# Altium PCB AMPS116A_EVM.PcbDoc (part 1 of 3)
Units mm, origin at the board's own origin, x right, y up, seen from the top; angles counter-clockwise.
Board outline 95 x 85 mm, 4 copper layers (Top Layer, Mid-Layer 1, Mid-Layer 2, Bottom Layer), stack 1.554 mm thick; 252 components, 134 nets, 806 pads, 625 vias.
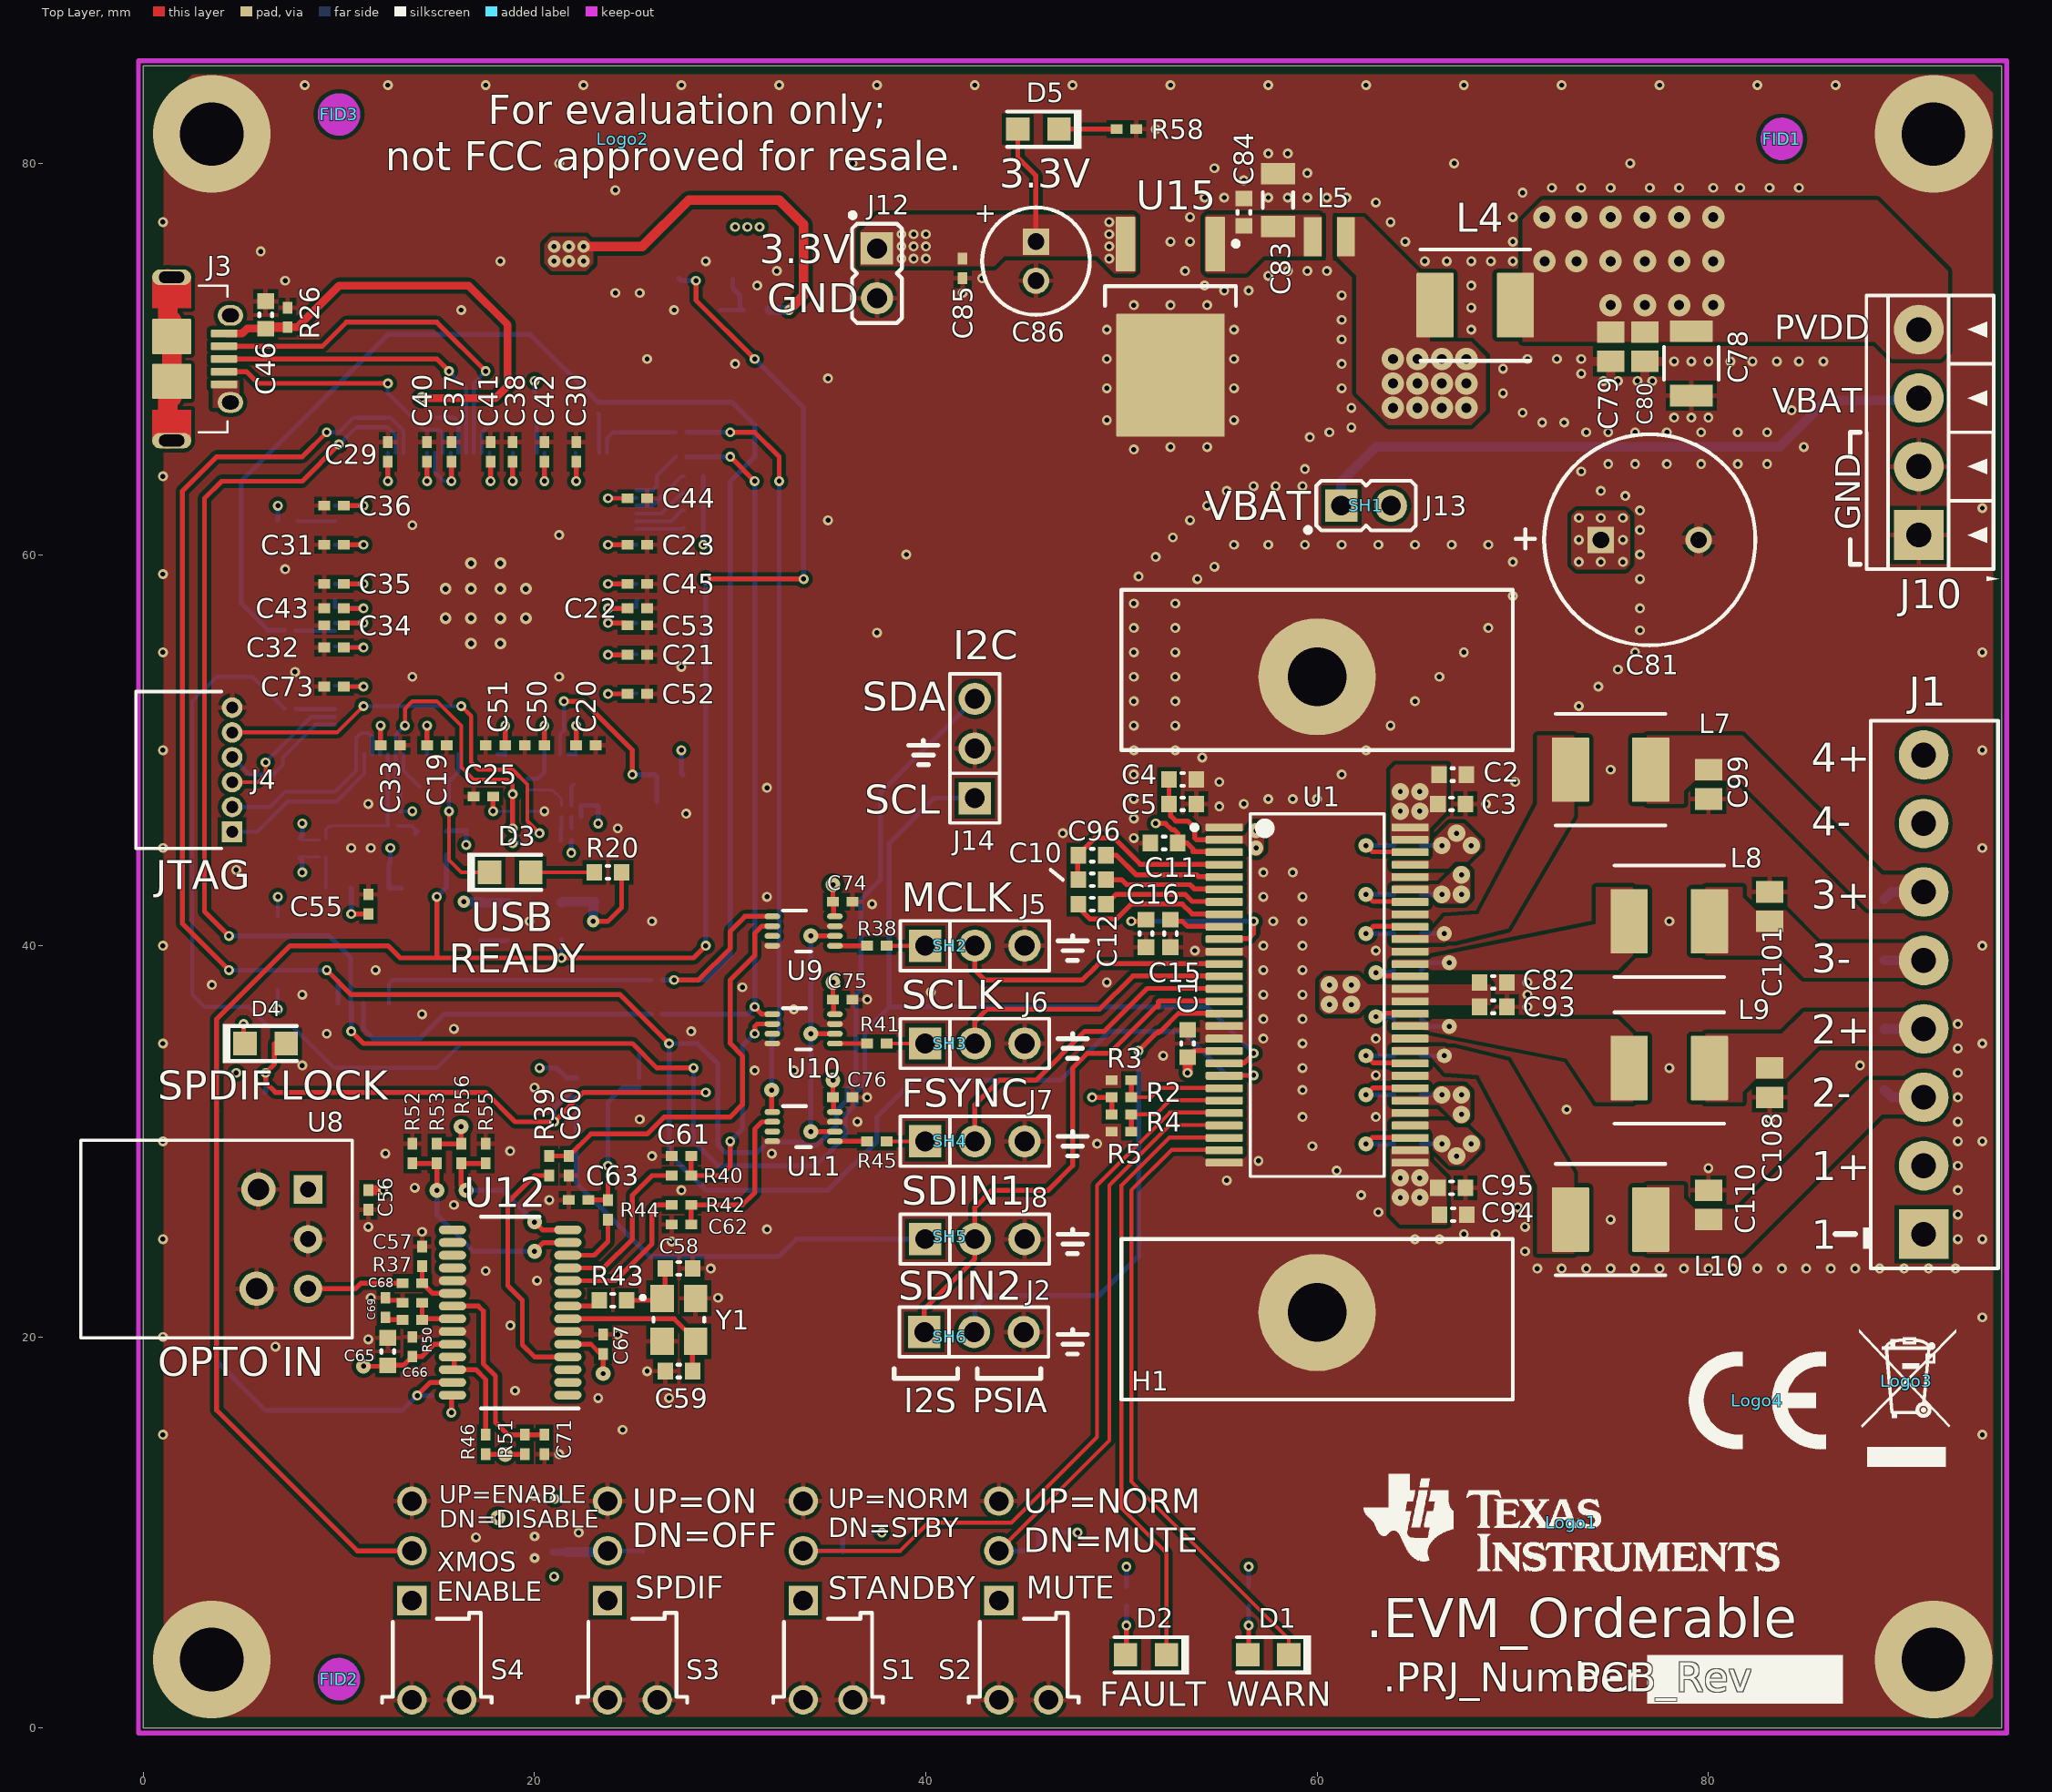
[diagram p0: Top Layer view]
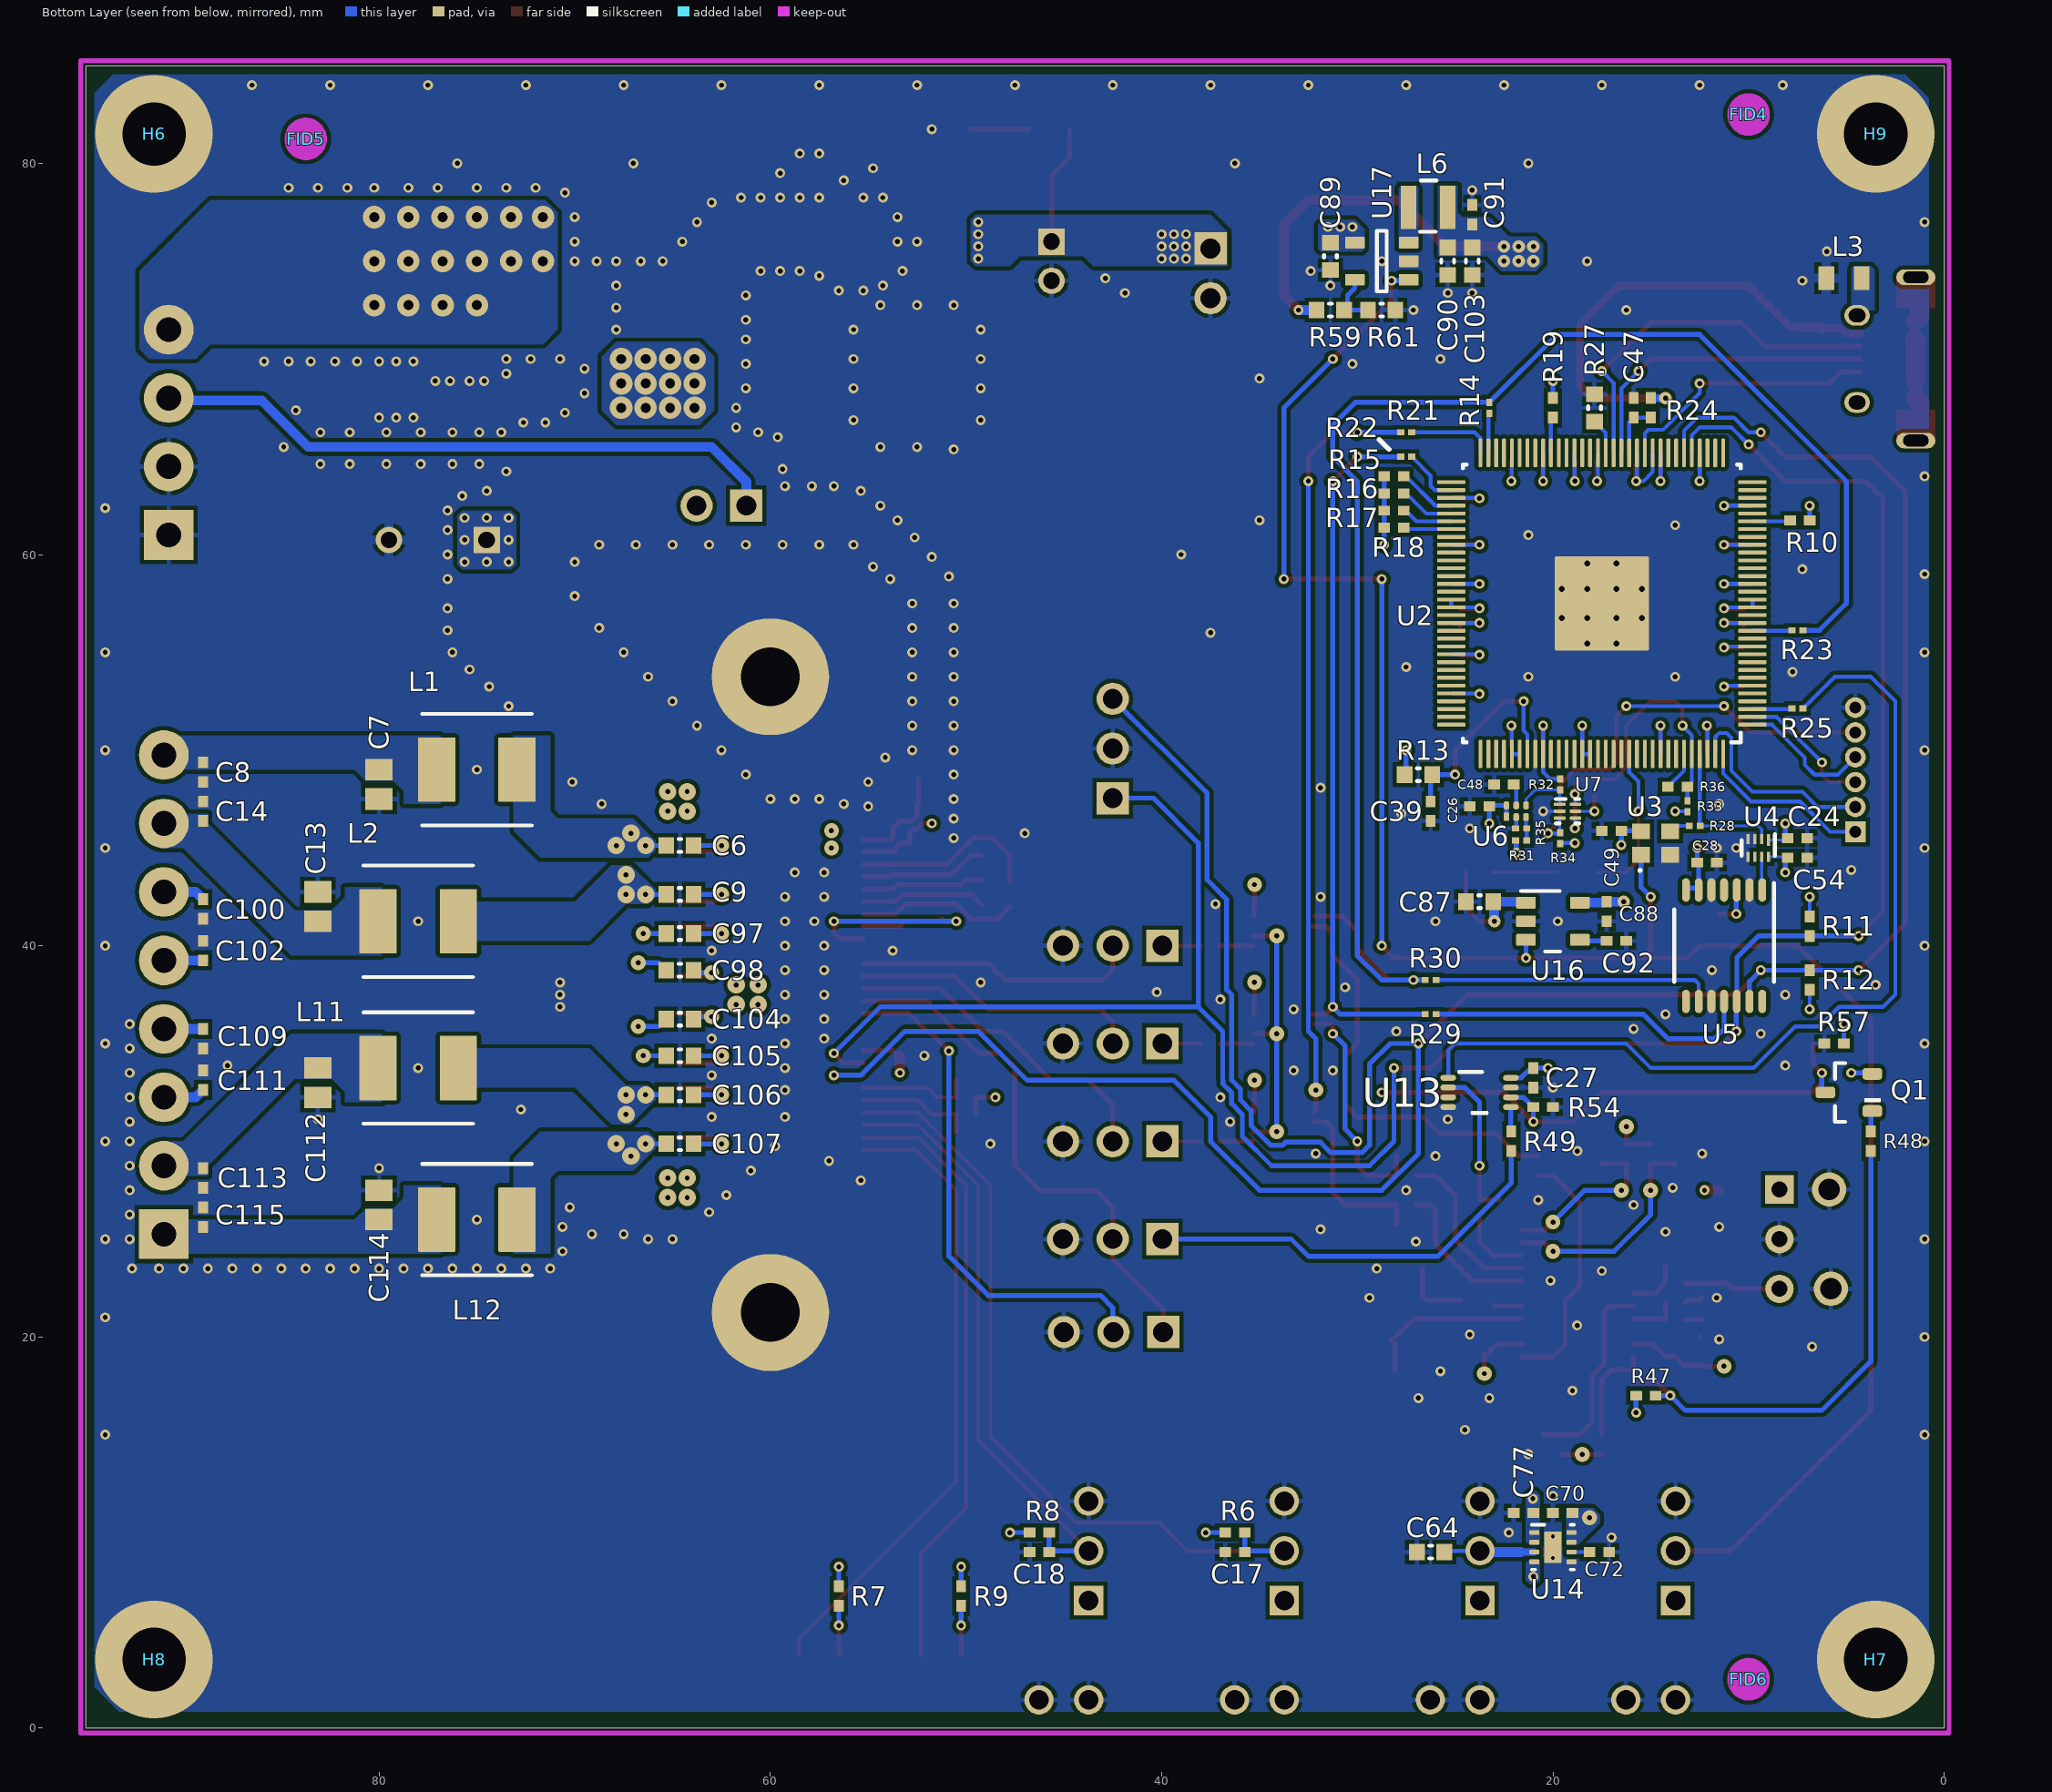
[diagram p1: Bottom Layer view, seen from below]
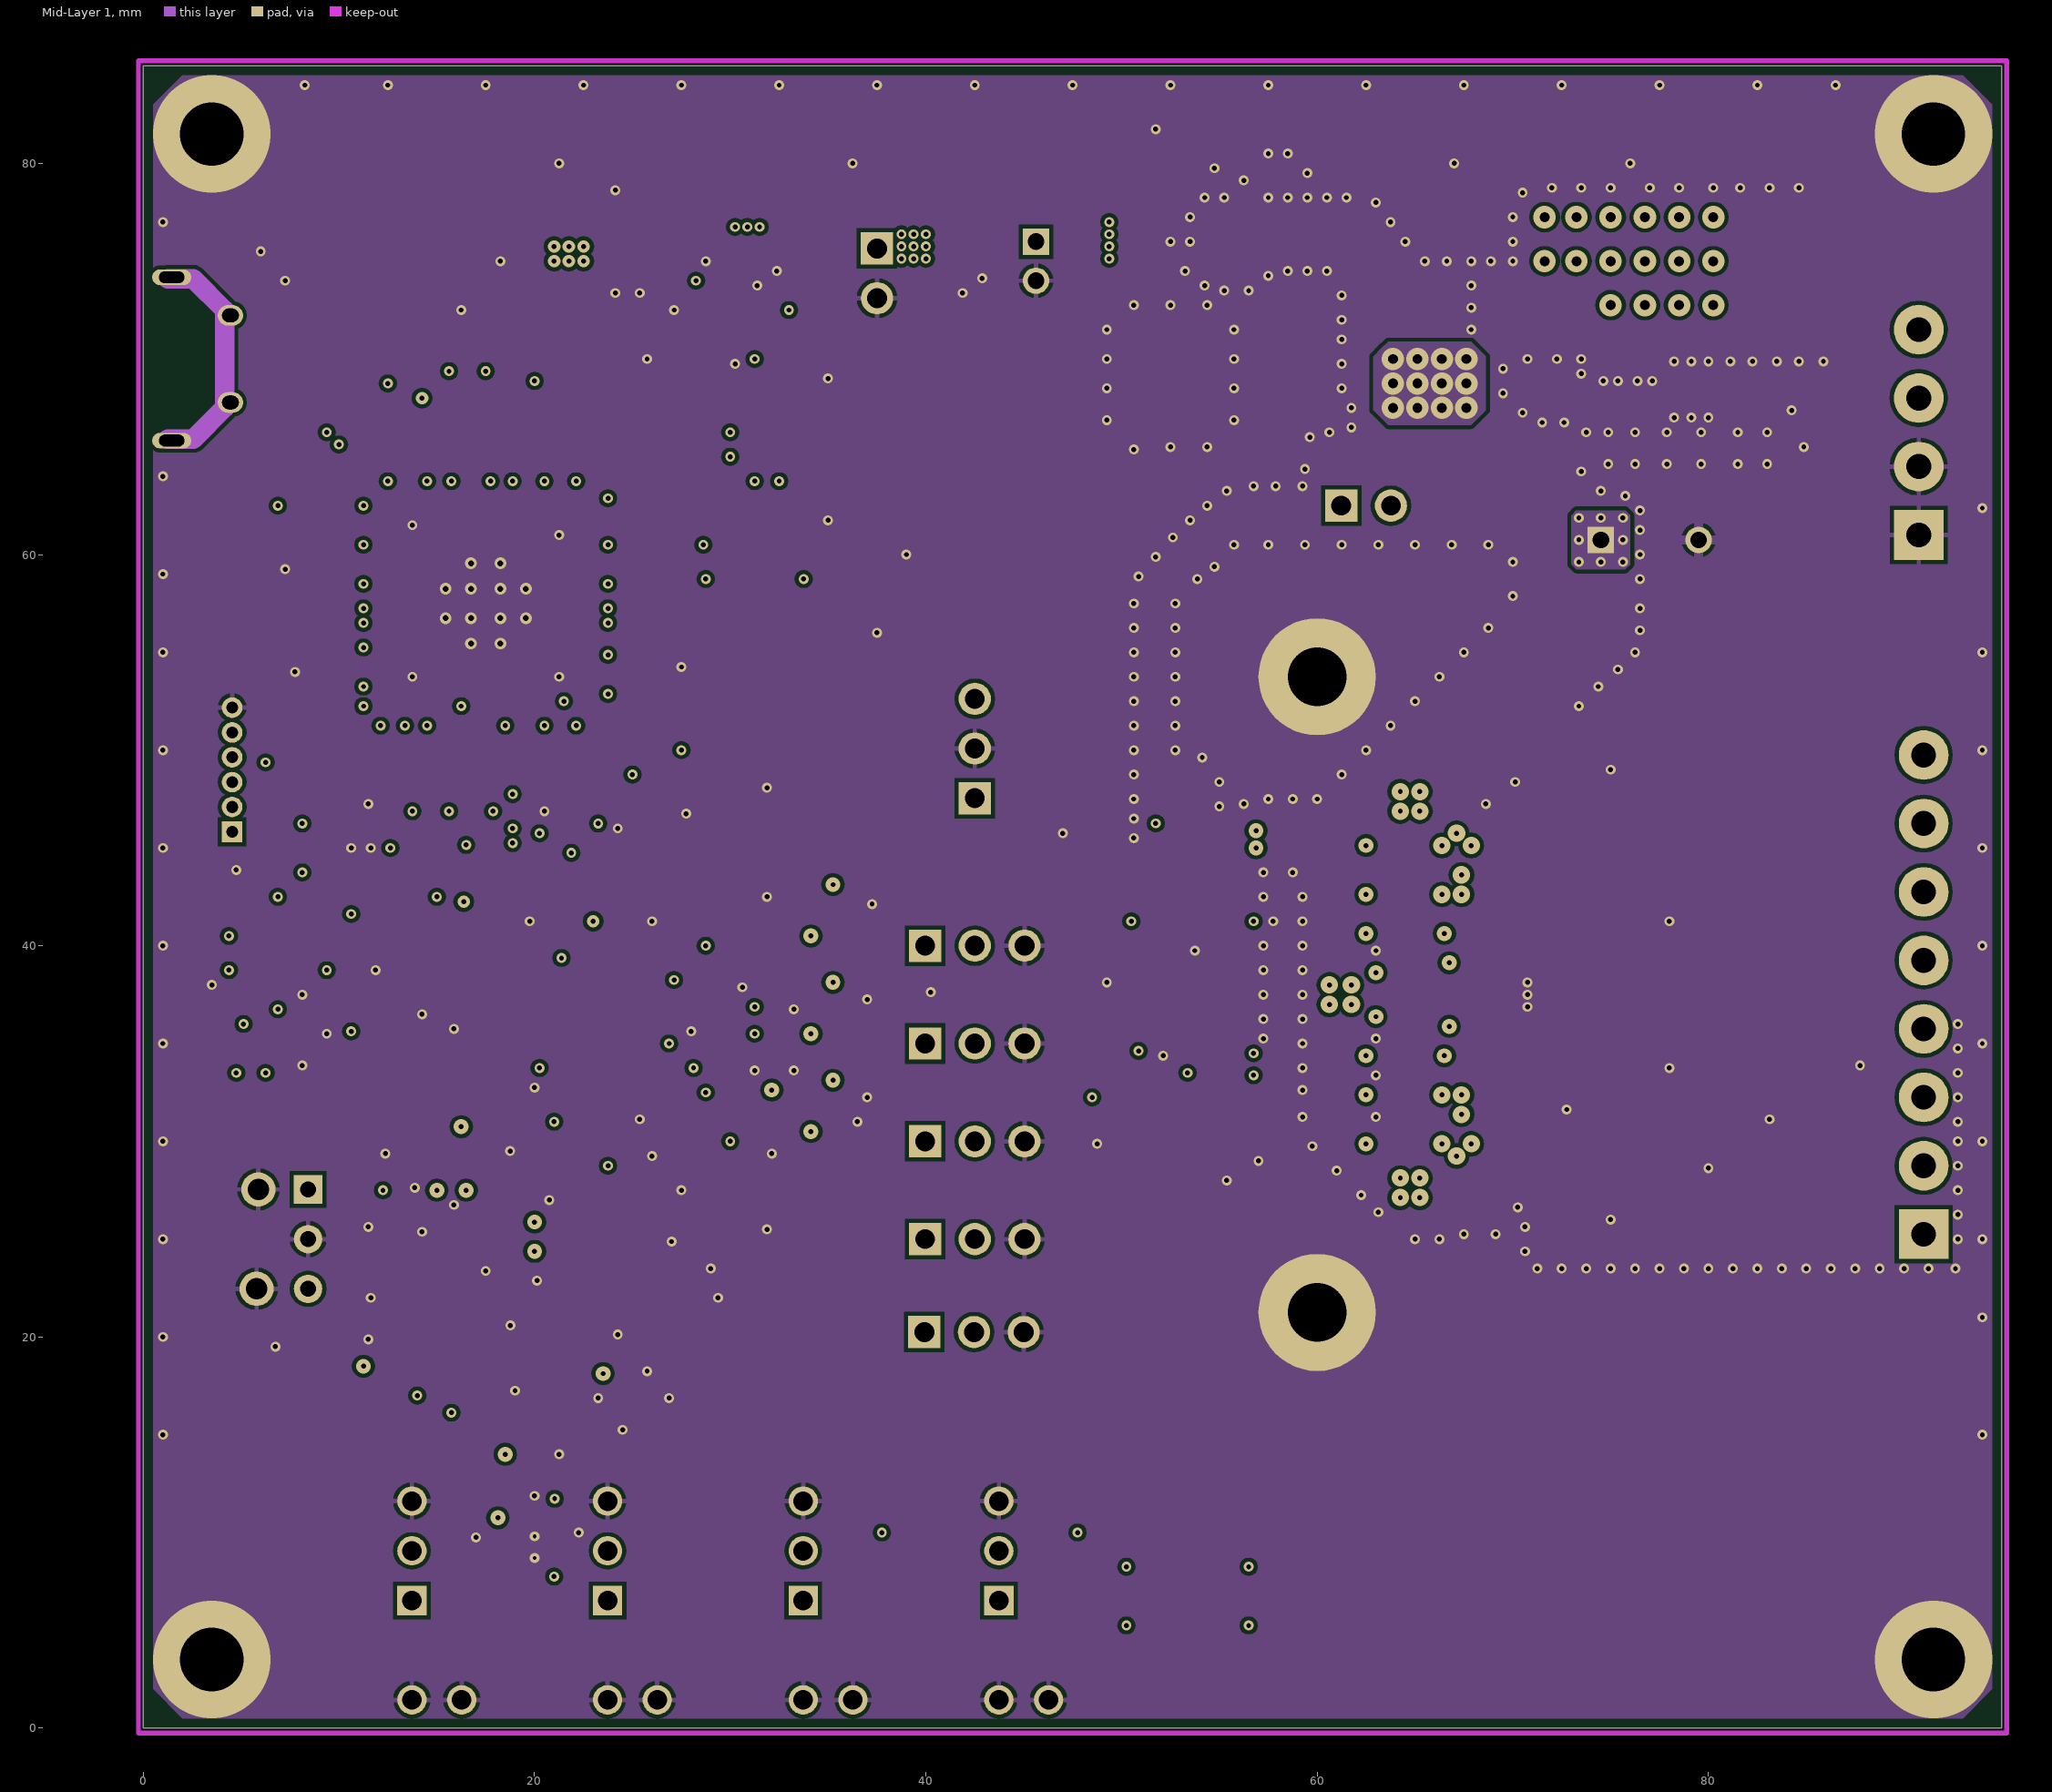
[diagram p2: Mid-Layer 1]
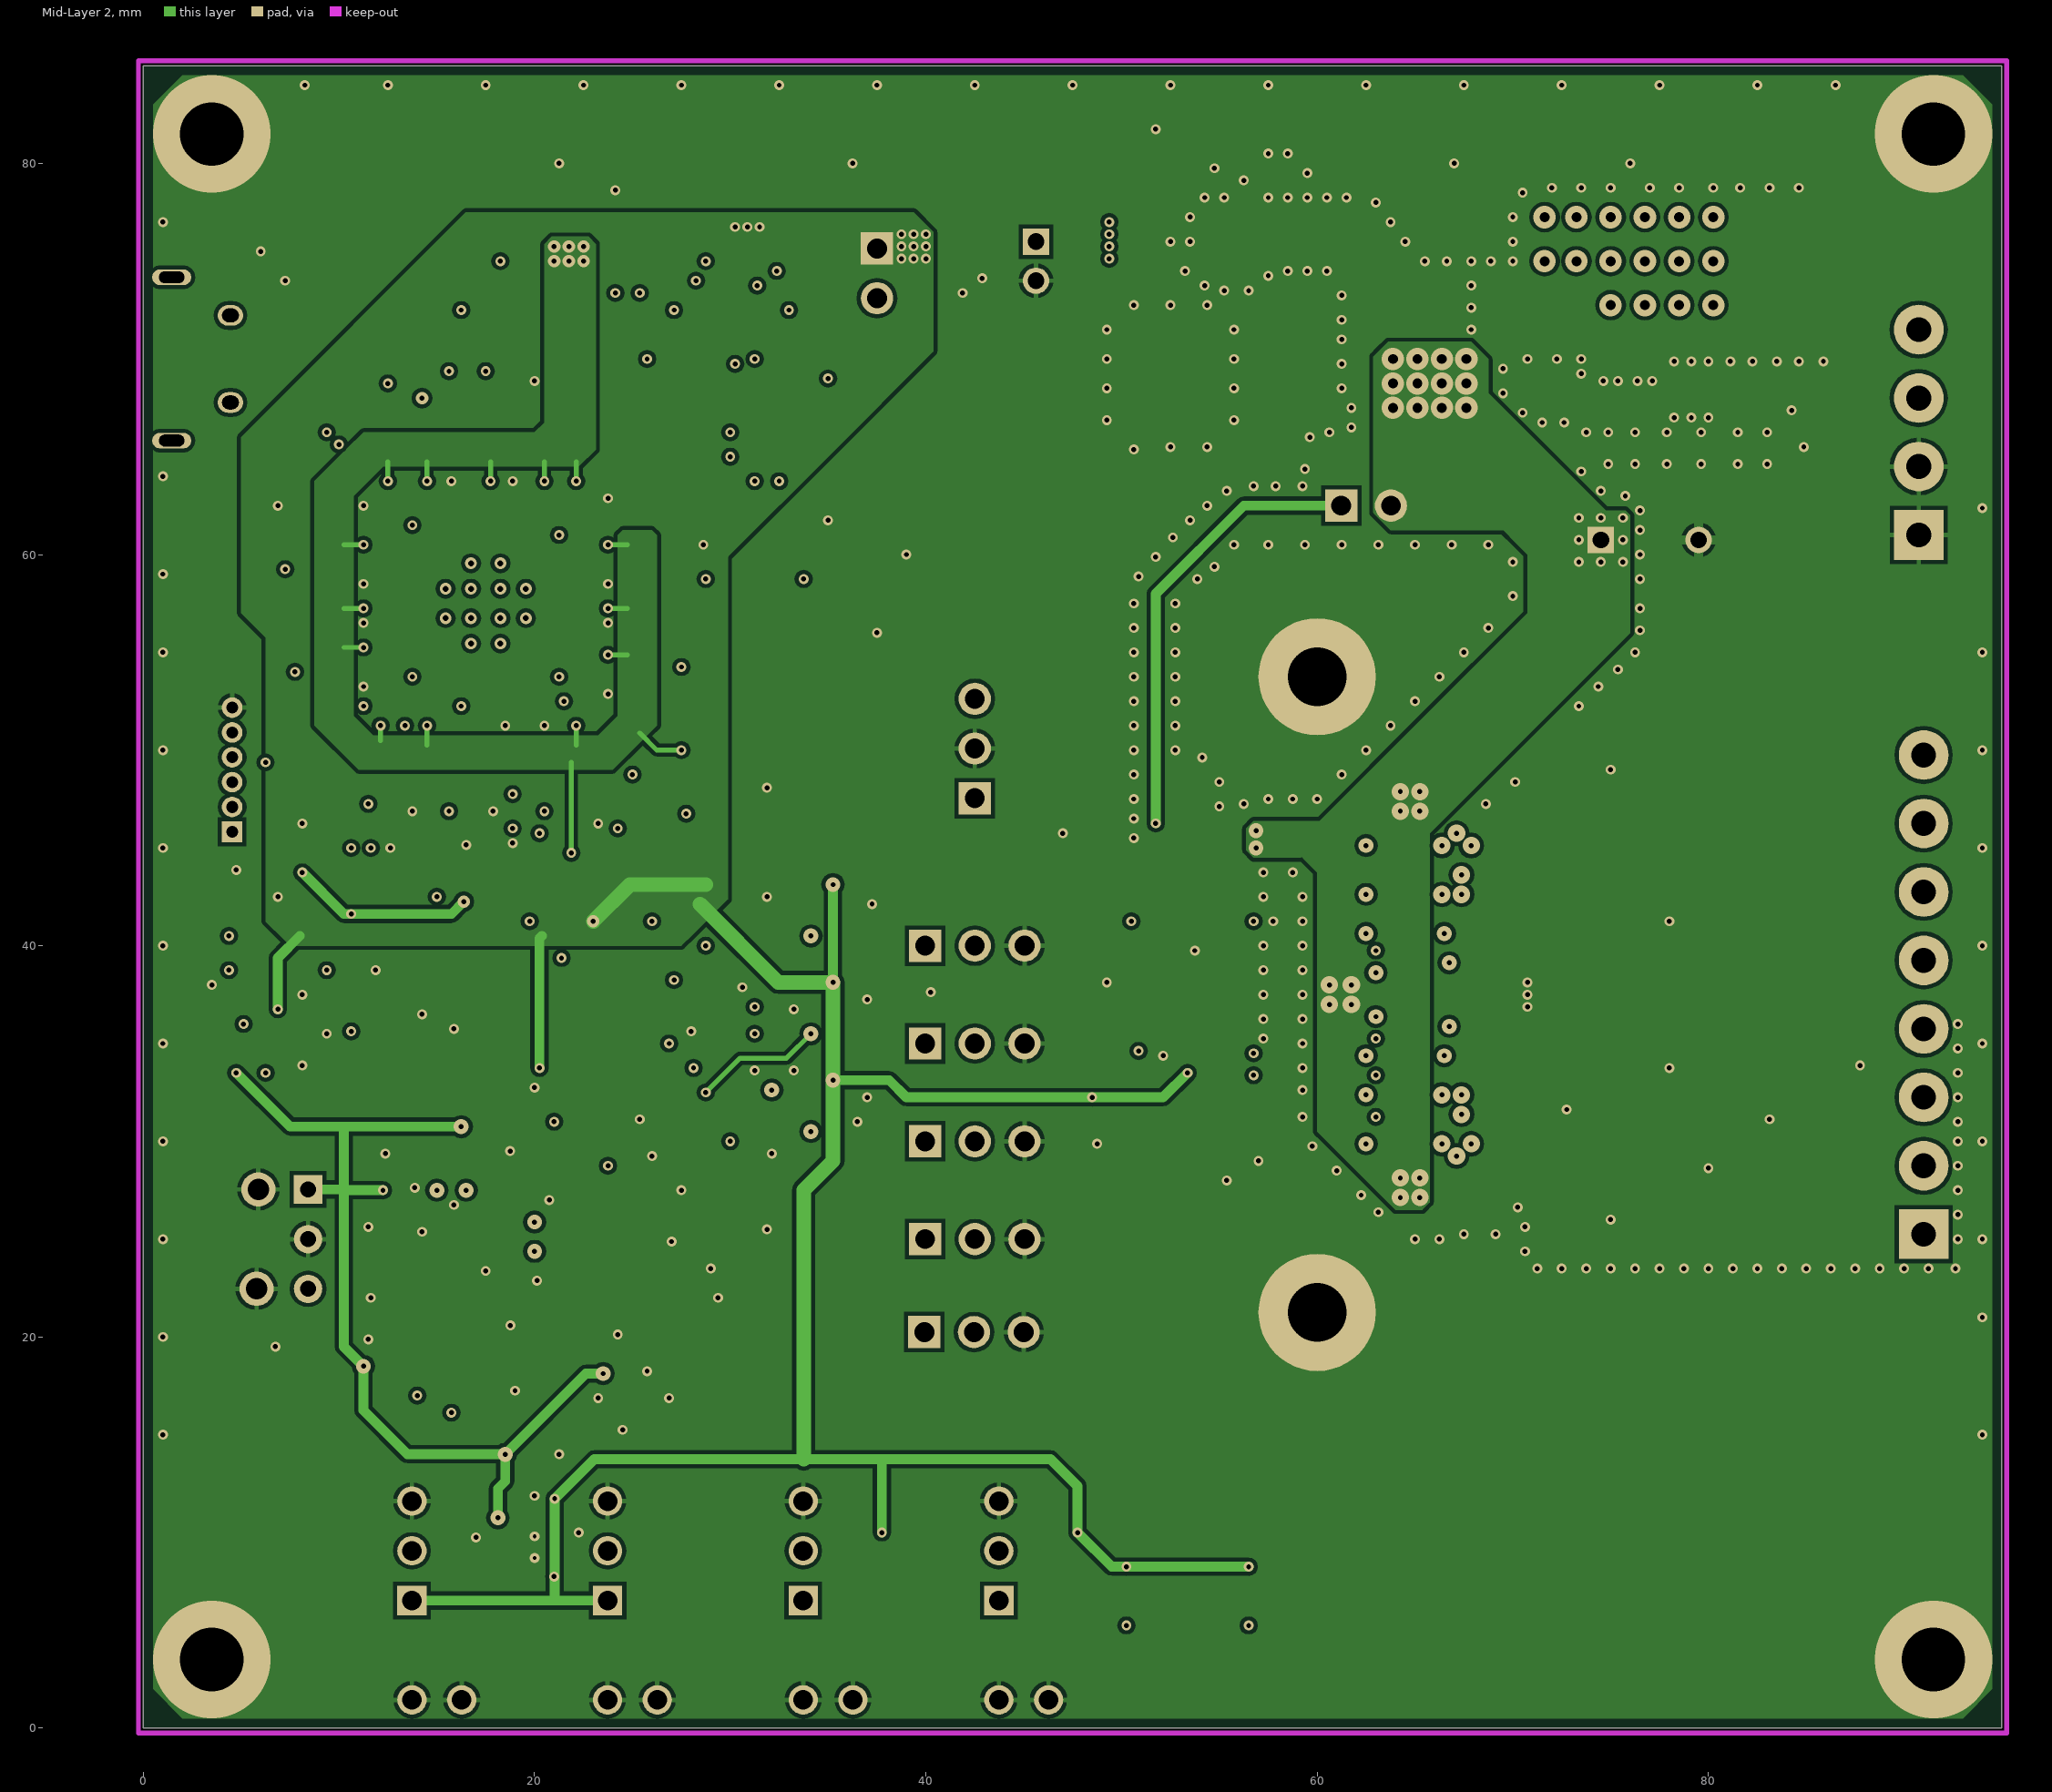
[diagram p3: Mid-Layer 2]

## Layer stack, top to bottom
Top Solder: solder mask 0.0102, Solder Resist, Dk 3.5
Top Layer: signal copper 0.0356
Dielectric1: core 0.2032, FR-4, Dk 4.2
Mid-Layer 1: signal copper 0.0356
Dielectric3: dielectric 1.0058, FR-4, Dk 4.2
Mid-Layer 2: signal copper 0.0356
Dielectric2: dielectric 0.2032, FR-4, Dk 4.2
Bottom Layer: signal copper 0.0356
Bottom Solder: solder mask 0.0102, Solder Resist, Dk 3.5

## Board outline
0,0 95,0 95,85 0,85

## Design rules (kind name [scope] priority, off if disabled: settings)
AcuteAngle [All] p1: minimum=4.50000000000000E+0001 checktracksonly=FALSE
AssemblyTestPointUsage [All] p1: valid=2
BoardOutlineClearance "Parts At Edge" [(InComponentClass('Edge Parts'))] p1: gap=0 ignorepadtopadclearanceinfootprint=FALSE
BoardOutlineClearance BoardOutlineClearance_MountingHoles [OnCopper and InComponentClass('Mounting Holes')] p2: gap=0.25 ignorepadtopadclearanceinfootprint=FALSE
BoardOutlineClearance BoardOutlineClearance_Poly [OnCopper and IsPoly] p3: gap=0.45 ignorepadtopadclearanceinfootprint=FALSE
BoardOutlineClearance [OnCopper and Not InComponentClass('Logo') and not InComponentClass('FiducialMark') and not InRegion(1000,500,4000,800) and not InPoly] p4: gap=0.25 ignorepadtopadclearanceinfootprint=FALSE
Clearance "Clearance LibErrors" [HasFootprint('DSF*') or HasFootprint('DQE*') or HasFootprint('RLT*')] p1: gap=0.2 ignorepadtopadclearanceinfootprint=TRUE except(0: Arc-Hole Track-Hole SMDPad-Hole THPad-Hole Via-Hole Fill-Hole Poly-Hole Region-Hole Text-Hole; 0.15: Arc-Arc Arc-Track Arc-SMDPad Track-Track Track-SMDPad)
Clearance Clearance_Keepouts [((IsTrack Or IsArc) And Not InPoly) And IsFree and IsKeepOut vs ((IsTrack Or IsArc) And Not InPoly) And IsFree and IsKeepOut] p2: gap=0 ignorepadtopadclearanceinfootprint=FALSE
Clearance Clearance_Poly [InPolygon] p3: gap=0.2 ignorepadtopadclearanceinfootprint=FALSE except(0: Arc-Hole Track-Hole SMDPad-Hole THPad-Hole Via-Hole Fill-Hole Poly-Hole Region-Hole Text-Hole)
Clearance Clearance_FiducialMark [IsKeepOut and InComponentClass('FiducialMark') vs IsPad and InComponentClass('FiducialMark')] p4: gap=0 ignorepadtopadclearanceinfootprint=FALSE
Clearance [All] p5: gap=0.2 ignorepadtopadclearanceinfootprint=FALSE except(0: Arc-Hole Track-Hole SMDPad-Hole THPad-Hole Via-Hole Fill-Hole Poly-Hole Region-Hole Text-Hole)
ComponentClearance "HeatSink Clearance" [InComponentClass('HeatSink')] p1: gap=0 collisioncheckmode=3 verticalgap=0 showdistances=FALSE
ComponentClearance ComponentClearance_MountingHoles_FiducialMarks [InComponentClass('Mounting Holes') vs InComponentClass('FiducialMark')] p2: gap=0.25 collisioncheckmode=3 verticalgap=0 showdistances=FALSE
ComponentClearance ComponentClearance_Shunt [InComponentClass('Header') vs InComponentClass('Shunt')] p3: gap=0 collisioncheckmode=3 verticalgap=0 showdistances=FALSE
ComponentClearance ComponentClearance_Logo [InComponentClass('Logo')] p4: gap=0.25 collisioncheckmode=3 verticalgap=0 showdistances=FALSE
ComponentClearance ComponentClearance_MountingHoles [InComponentClass('Mounting Holes') vs InComponentClass('Mounting Holes')] p5: gap=0 collisioncheckmode=3 verticalgap=0 showdistances=FALSE
ComponentClearance ComponentClearance_SmallPassives [HasFootprint('0201*') or HasFootprint('0402*') or HasFootprint('0603*') or HasFootprint('0805*') or HasFootprint('1008*') or HasFootprint('12*') or HasFootprint('Abracon*') or HasFootprint('DBV*') or HasFootprint('DCU*') or HasFootprint('DFE*') or HasFootprint('DS*') or HasFootprint('DQE*') or HasFootprint('DRY*') or HasFootprint('FDSD*') or HasFootprint('KVU*') or HasFootprint('NFZ*') or HasFootprint('PW*') or HasFootprint('RLT*') or HasFootprint('SOT*') or HasFootprint('SW*') or HasFootprint('VLS*') vs HasFootprint('0201*') or HasFootprint('0402*') or HasFootprint('0603*') or HasFootprint('0805*') or HasFootprint('1008*') or HasFootprint('12*') or HasFootprint('Abracon*') or HasFootprint('DBV*') or HasFootprint('DCU*') or HasFootprint('DFE*') or HasFootprint('DS*') or HasFootprint('DQE*') or HasFootprint('DRY*') or HasFootprint('FDSD*') or HasFootprint('KVU*') or HasFootprint('NFZ*') or HasFootprint('PW*') or HasFootprint('RLT*') or HasFootprint('SOT*') or HasFootprint('SW*') or HasFootprint('VLS*')] p6: gap=0.2 collisioncheckmode=3 verticalgap=0 showdistances=FALSE
ComponentClearance ComponentClearance_THtoSMT [IsThruComponent vs IsSMTComponent] p7: gap=0.25 collisioncheckmode=3 verticalgap=0 showdistances=FALSE
ComponentClearance ComponentClearance_THtoTH [IsThruComponent vs IsThruComponent] p8: gap=0.25 collisioncheckmode=3 verticalgap=0 showdistances=FALSE
ComponentClearance [All] p9: gap=0.762 collisioncheckmode=3 verticalgap=0.254 showdistances=FALSE
DiffPairsRouting [All] p1: maxlimit=2.54 minlimit=0.254 mostfreqgap=0.254 toplayer_minwidth=0.381 toplayer_maxwidth=0.381 toplayer_prefwidth=0.381 midlayer1_minwidth=0.381 midlayer1_maxwidth=0.381 midlayer1_prefwidth=0.381 midlayer2_minwidth=0.381 midlayer2_maxwidth=0.381 midlayer2_prefwidth=0.381 bottomlayer_minwidth=0.381 bottomlayer_maxwidth=0.381 bottomlayer_prefwidth=0.381 maxuncoupledlength=25.4
FabricationTestPointUsage TestPointUsage [All] p1: valid=2 allowmultiple=FALSE
FabricationTestpoint Testpoint [All] p1: side=3 testpointundercomponent=TRUE minsize=1.016 maxsize=2.54 preferedsize=1.524 minholesize=0 maxholesize=1.016 preferedholesize=0.813 testpointgrid=0.025 allowsidetop=TRUE allowsidebottom=TRUE usegrid=TRUE gridtolerance=0
FanoutControl Fanout_LCC [IsLCC] p1: bgadir=Out bgaviamode=Centered fanoutstyle=Auto fanoutdirection=Alternating viagrid=0.025 // Fanout_LCC (Default Rule)
FanoutControl Fanout_BGA [IsBGA] p2: bgadir=Out bgaviamode=Centered fanoutstyle=Auto fanoutdirection=Alternating viagrid=0.025 // Fanout_BGA (Default Rule)
FanoutControl Fanout_Default [All] p4: bgadir=Out bgaviamode=Centered fanoutstyle=Auto fanoutdirection=Alternating viagrid=0.025 // Fanout_Default (Default Rule)
FanoutControl Fanout_Small [(CompPinCount < 5)] p5: bgadir=Out bgaviamode=Centered fanoutstyle=Auto fanoutdirection=OutThenIn viagrid=0.025 // Fanout_Small (Default Rule)
Height [All] p1: minheight=0 maxheight=35 prefheight=12.7
HoleSize [All] p1: absolutevalues=TRUE maxlimit=6.375 minlimit=0.2 maxpercent=80.000 minpercent=20.000
MinimumAnnularRing MinimumAnnularRing_ThermalPadVias [IsVia and InAnyComponent] p1: minimumring=0.15
MinimumAnnularRing [All] p2: minimumring=0.127
MinimumSolderMaskSliver "MinSolderMaskSliver LibErrors" [HasFootprint('DSF*') or HasFootprint('DQE*')] p1: minsoldermaskwidth=0.064
MinimumSolderMaskSliver MinimumSolderMaskSliver_Logo [InComponentClass('Logo') vs InComponentClass('Logo')] p2: minsoldermaskwidth=0.018
MinimumSolderMaskSliver [All] p3: minsoldermaskwidth=0.1
PlaneConnect [All] p1: planeconnectstyle=Relief reliefexpansion=0.254 reliefentries=4 reliefconductorwidth=0.254 reliefairgap=0.254
PolygonConnect "Post GND Full Flood" [InComponentClass('GND Full Flood') vs InNet('GND')] p1: connectstyle=Direct reliefconductorwidth=0.254 reliefentries=4 polygonreliefangle="90 Angle" airgapwidth=0.254
PolygonConnect "GND Thermals 0.5mm" [InComponentClass('GND Thermals 0.5mm') vs InNet('GND')] p2: connectstyle=Relief reliefconductorwidth=0.5 reliefentries=4 polygonreliefangle="90 Angle" airgapwidth=0.2
PolygonConnect "GND Thermals 0.25mm" [InComponent('C*') or InComponent('D*') or InComponent('J*') or  InComponent('R*') or InComponent('S*') or InComponent('TP*') or  InComponent('Y*') or InComponent('U8') or InComponent('U16') vs InNet('GND')] p3: connectstyle=Relief reliefconductorwidth=0.25 reliefentries=4 polygonreliefangle="90 Angle" airgapwidth=0.2
PolygonConnect "Pre Flood" [All] p4: connectstyle=Direct reliefconductorwidth=0.254 reliefentries=4 polygonreliefangle="90 Angle" airgapwidth=0.254
RoutingVias ThermalPadVias [IsVia and InAnyComponent] p1: holewidth=0.2 width=0.5 viastyle="Through Hole" minholewidth=0.2 minwidth=0.5 maxholewidth=0.33 maxwidth=0.6
RoutingVias [All] p2: holewidth=0.254 width=0.508 viastyle="Through Hole" minholewidth=0.2 minwidth=0.508 maxholewidth=3.25 maxwidth=6.5
SilkToBoardRegionClearance [Not ((IsComment or IsDesignator) And (Hide <> 'False')) and not InRegion(1000,500,4000,800)] p1:
SilkToSilkClearance SilkToSilkClearance_Pb-FreeLogo [(HasFootprint('Pb-Free_Overlay_Medium') OR HasFootprint('Pb-Free_Overlay_Small')) vs (HasFootprint('Pb-Free_Overlay_Medium') OR HasFootprint('Pb-Free_Overlay_Small'))] p1: silktosilkclearance=0
SilkToSilkClearance [All] p2: silktosilkclearance=0.102
SilkToSolderMaskClearance "SilkToSolderMask LibErrors" [All vs HasFootprint('DSF*') or HasFootprint('LED*') or HasFootprint('LTST*')] p1: minsilkscreentomaskgap=0.038 clearancetoexposedcopper=FALSE
SilkToSolderMaskClearance SilkToComponentPadClearance [(IsPad or IsFill or IsRegion) and InAnycomponent] p2: minsilkscreentomaskgap=0.127 clearancetoexposedcopper=TRUE
SilkToSolderMaskClearance "Silk to Solder Mask Opening" [All] p3: minsilkscreentomaskgap=0.102 clearancetoexposedcopper=FALSE
SolderMaskExpansion [All] p1: expansion=0.05
Width [All] p1: maxlimit=2 minlimit=0.15 preferedwidth=0.25 toplayer_prefwidth=0.2 midlayer1_minwidth=0.2 midlayer1_maxwidth=1 midlayer2_minwidth=0.2 midlayer2_maxwidth=1 bottomlayer_prefwidth=0.2 minimp=50.000000 maximp=50.000000 favimp=50.000000 checkconnectedcopper=TRUE
14 further rules are at their usual default settings.

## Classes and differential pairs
component class "GND Thermals Full Flood": C89 C90 C91 C103
component class "GND Thermals 0.5mm": C79 C80 C81 L3
component class "GND Full Flood": C2 C4 C8 C14 C82 C83 C84 C94 C100 C102 C109 C111 C113 C115 R3 R5
component class Shunt: SH1 SH2 SH3 SH4 SH5 SH6
component class Header: J2 J5 J6 J7 J8 J12 J13 J14
component class AMPS116A_USB: C19 C20 C21 C22 C23 C24 C25 C26 C27 C28 C29 C30 C31 C32 C33 C34 C35 C36 C37 C38 C39 C40 C41 C42 C43 C44 C45 C46 C47 C48 C49 C50 C51 C52 C53 C54 C55 C117 C120 C121 C122 C123 D3 J3 J4 L3 R10 R11 R12 R13 R14 R15 R16 R17 R18 R19 R20 R21 R22 R23 R24 R25 R26 R27 R28 R29 R30 R31 R32 R33 R34 R35 R36 R62 R63 U2 U3 U4 U5 U6 U7
component class AMPS116A_TAS6424-IO: C1 C2 C3 C4 C5 C6 C7 C8 C9 C10 C11 C12 C13 C14 C15 C16 C17 C18 C82 C93 C94 C95 C96 C97 C98 C99 C100 C101 C102 C104 C105 C106 C107 C108 C109 C110 C111 C112 C113 C114 C115 D1 D2 H1 J1 J2 J13 J14 L1 L2 L7 L8 L9 L10 L11 L12 R2 R3 R4 R5 R6 R7 R8 R9 S1 S2 U1
component class AMPS116A_SPDIF: C56 C57 C58 C59 C60 C61 C62 C63 C64 C65 C66 C67 C68 C69 C70 C71 C72 C73 C74 C75 C76 C77 D4 J5 J6 J7 J8 Q1 R37 R38 R39 R40 R41 R42 R43 R44 R45 R46 R47 R48 R49 R50 R51 R52 R53 R54 R55 R56 R57 S3 U8 U9 U10 U11 U12 U13 U14 Y1
component class AMPS116A_PowerSupplies: C78 C79 C80 C81 C83 C84 C85 C86 C87 C88 C89 C90 C91 C92 C103 D5 J10 J12 L4 L5 L6 R58 R59 R61 S4 U15 U16 U17
component class AssemblyNote: ZZ1 ZZ2 ZZ3 ZZ4 ZZ5
component class FiducialMark: FID1 FID2 FID3 FID4 FID5 FID6
component class AMPS116A_EVM_Hardware: FID1 FID2 FID3 FID4 FID5 FID6 H6 H7 H8 H9 Logo1 Logo2 Logo3 Logo4 SH1 SH2 SH3 SH4 SH5 SH6 ZZ1 ZZ2 ZZ3 ZZ4 ZZ5
component class Logo: Logo1
component class HeatSink: H1

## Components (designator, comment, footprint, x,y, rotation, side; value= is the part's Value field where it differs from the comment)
C1 "C0603C105K3RACTU" 0603L 53.375,35 r270 top value=1uF
C2 "Capacitor" 0603L 66.925,48.75 r0 top value=1uF
C3 "C0603C104K5RACTU" 0603L 66.875,47.25 r180 top value=0.1uF
C4 "Capacitor" 0603L 53.125,48.5 r0 top value=1uF
C5 "C0603C104K5RACTU" 0603L 53.125,47.25 r180 top value=0.1uF
C6 "EMK107BB7225KA-T" 0603L 64.625,45.125 r0 bottom value=2.2uF
C7 "C0805C105K5RACTU" 0805L 80,48.25 r270 bottom value=1uF
C8 "Capacitor" 0402L 89,48.875 r90 bottom value=0.01uF
C9 "EMK107BB7225KA-T" 0603L 64.625,42.625 r0 bottom value=2.2uF
C10 "C0603C105K3RACTU" 0603L 48.5,43.375 r0 top value=1uF
C11 "C0603C104K5RACTU" 0603L 52.175,45.25 r0 top value=0.1uF
C12 "C0603C105K3RACTU" 0603L 48.5,42.125 r180 top value=1uF
C13 "C0805C105K5RACTU" 0805L 83.125,42 r90 bottom value=1uF
C14 "Capacitor" 0402L 89,46.875 r270 bottom value=0.01uF
C15 "EMK107BB7225KA-T" 0603L 52.5,40.625 r90 top value=2.2uF
C16 "EMK107BB7225KA-T" 0603L 51.25,40.625 r90 top value=2.2uF
C17 "C0402C104K4RACAUTO" 0402L 36.25,9 r0 bottom value=0.1uF
C18 "C0402C104K4RACAUTO" 0402L 46.25,9 r0 bottom value=0.1uF
C19 "Capacitor" 0402L 15,50.25 r180 top value=0.1uF
C20 "Capacitor" 0402L 22.625,50.25 r180 top value=0.1uF
C21 "Capacitor" 0402L 25.25,54.875 r180 top value=0.1uF
C22 "Capacitor" 0402L 25.25,57.25 r180 top value=0.1uF
C23 "Capacitor" 0402L 25.25,60.5 r180 top value=0.1uF
C24 "C1005X7R1H104K050BB" 0402L 7.5,45.5 r180 bottom value=0.1uF
C25 "C1005X7R1H104K050BB" 0402L 17.375,47.625 r180 top value=0.1uF
C26 "C1005X7R1H104K050BB" 0402L 23.75,47.125 r0 bottom value=0.1uF
C27 "C1005X7R1H104K050BB" 0402L 21,33.25 r270 bottom value=0.1uF
C28 "C1005X7R1H104K050BB" 0402L 12.125,44.25 r180 bottom value=0.1uF
C29 "Capacitor" 0402L 12.5,65.25 r270 top value=0.1uF
C30 "Capacitor" 0402L 22.125,65.25 r270 top value=0.1uF
C31 "Capacitor" 0402L 9.75,60.5 r0 top value=0.1uF
C32 "Capacitor" 0402L 9.75,55.25 r0 top value=0.1uF
C33 "Capacitor" 0402L 12.625,50.25 r180 top value=0.1uF
C34 "C1005X7R1H104K050BB" 0402L 9.75,56.375 r180 top value=0.1uF
C35 "C1005X7R1H104K050BB" 0402L 9.75,58.5 r180 top value=0.1uF
C36 "C1005X7R1H104K050BB" 0402L 9.75,62.5 r180 top value=0.1uF
C37 "C1005X7R1H104K050BB" 0402L 15.75,65.25 r90 top value=0.1uF
C38 "C1005X7R1H104K050BB" 0402L 18.875,65.25 r90 top value=0.1uF
C39 "C1005X7R1H104K050BB" 0402L 26.25,46.875 r270 bottom value=0.1uF
C40 "Capacitor" 0402L 14.5,65.25 r270 top value=0.1uF
C41 "Capacitor" 0402L 17.75,65.25 r270 top value=0.1uF
C42 "Capacitor" 0402L 20.5,65.25 r270 top value=0.1uF
C43 "Capacitor" 0402L 9.75,57.25 r0 top value=0.1uF
C44 "C1005X7R1H104K050BB" 0402L 25.25,62.875 r0 top value=0.1uF
C45 "C1005X7R1H104K050BB" 0402L 25.25,58.5 r0 top value=0.1uF
C46 "EMK107BB7225MA-T" 0603L 6.25,72.25 r90 top value=2.2uF
C47 "C1005X7R1H104K050BB" 0402L 15.875,67.5 r90 bottom value=0.1uF
C48 "GRT1555C1H471JA02D" 0402L 22.5,48.25 r0 bottom value=470pF
C49 "C1005X7R1H104K050BB" 0402L 17,45.875 r0 bottom value=0.1uF
C50 "C1005X7R1H104K050BB" 0402L 20,50.25 r180 top value=0.1uF
C51 "C1005X7R1H104K050BB" 0402L 18,50.25 r180 top value=0.1uF
C52 "C1005X7R1H104K050BB" 0402L 25.25,52.875 r0 top value=0.1uF
C53 "C1005X7R1H104K050BB" 0402L 25.25,56.375 r0 top value=0.1uF
C54 "C1005X7R1H104K050BB" 0402L 7.5,44.5 r180 bottom value=0.1uF
C55 "C1005X7R1H104K050BB" 0402L 11.5,42.125 r90 top value=0.1uF
C56 "C0402C104K4RACAUTO" 0402L 11.5,27 r270 top value=0.1uF
C57 "885012005055" 0402L 14.25,24.125 r90 top value=10pF
C58 "C0603C180J5GACTU" 0603L 27.375,23.5 r0 top value=18pF
C59 "C0603C180J5GACTU" 0603L 27.375,18.25 r180 top value=18pF
C60 "885012005055" 0402L 21.75,28.75 r270 top value=10pF
C61 "885012005055" 0402L 27.5,29.25 r180 top value=10pF
C62 "885012005055" 0402L 27.5,25.75 r180 top value=10pF
C63 "885012005055" 0402L 22.25,27 r180 top value=10pF
C64 "Capacitor" 0603L 26.25,9 r0 bottom value=10uF
C65 "Capacitor" 0603L 12.5,19.25 r90 top value=10uF
C66 "C0402C104K4RACAUTO" 0402L 13.75,19.5 r270 top value=0.1uF
C67 "C0402C104K4RACAUTO" 0402L 23.5,19.625 r270 top value=0.1uF
C68 "CC0402KRX7R8BB472" 0402L 13.75,21.75 r180 top value=4700pF
C69 "CGA2B3X7R1H683K050BB" 0402L 12.375,21.5 r90 top value=0.068uF
C70 "C0402C104K4RACAUTO" 0402L 19.5,11 r0 bottom value=0.1uF
C71 "GRM152R60J105ME15D" 0402L 20.5,14.5 r90 top value=1uF
C72 "CGA2B2C0G1H101J050BA" 0402L 17.625,9 r180 bottom value=100pF
C73 "C0402C104K4RACAUTO" 0402L 9.75,53.25 r0 top value=0.1uF
C74 "C0402C104K4RACAUTO" 0402L 35.75,42.25 r180 top value=0.1uF
C75 "C0402C104K4RACAUTO" 0402L 35.75,37.25 r180 top value=0.1uF
C76 "C0402C104K4RACAUTO" 0402L 35.75,32.25 r180 top value=0.1uF
C77 "GRM152R60J105ME15D" 0402L 21.5,11 r180 bottom value=1uF
C78 "C1210C475K5RACAUTO" 1210_280 79.125,69.775 r90 top value=4.7uF
C79 "Capacitor" 0805L 75,70.625 r90 top value=0.082uF
C80 "08055A222JAT2A" 0805L 76.75,70.625 r270 top value=2200pF
C81 "+" BT_1000x2000 77,60.75 r0 top locked value=330uF
C82 "Capacitor" 0603L 69,38.125 r180 top value=1uF
C83 "UMK316BBJ106KL-T" 1206_190L 58,78.125 r90 top value=10uF
C84 "C0603C104J5RACTU" 0603L 56.25,77.5 r270 top value=0.1uF
C85 "C0402C104K4RACAUTO" 0402L 41.875,74.625 r90 top value=0.1uF
C86 "Cap_Polarized" FC_500x1100 45.625,75 r270 top value=47uF
C87 "CL10B105MO8NNWC" 0603L 23.75,42.25 r180 bottom value=1uF
C88 "GRM152R60J105ME15D" 0402L 17.25,41.75 r90 bottom value=1uF
C89 "C1608X5R1A226M080AC" 0603L 31.375,75.25 r270 bottom value=22uF
C90 "C1608X5R1A226M080AC" 0603L 25.375,75 r270 bottom value=22uF
C91 "C1005X7R1H104K050BB" 0402L 24.125,77.375 r90 bottom value=0.1uF
C92 "0402B103K6R3CT" 0402L 16.75,40.25 r0 bottom value=0.01uF
C93 "C0603C104K5RACTU" 0603L 69,36.875 r180 top value=0.1uF
C94 "Capacitor" 0603L 66.95,26.25 r0 top value=1uF
C95 "C0603C104K5RACTU" 0603L 66.875,27.625 r180 top value=0.1uF
C96 "C0603C105K3RACTU" 0603L 48.5,44.625 r0 top value=1uF
C97 "EMK107BB7225KA-T" 0603L 64.625,40.625 r0 bottom value=2.2uF
C98 "EMK107BB7225KA-T" 0603L 64.625,38.75 r0 bottom value=2.2uF
C99 "C0805C105K5RACTU" 0805L 80,48.25 r270 top value=1uF
C100 "Capacitor" 0402L 89,41.875 r90 bottom value=0.01uF
C101 "C0805C105K5RACTU" 0805L 83.125,42 r90 top value=1uF
C102 "Capacitor" 0402L 89,39.75 r270 bottom value=0.01uF
C103 "C1608X5R1A226M080AC" 0603L 24.125,75 r270 bottom value=22uF
C104 "EMK107BB7225KA-T" 0603L 64.625,36.25 r0 bottom value=2.2uF
C105 "EMK107BB7225KA-T" 0603L 64.625,34.375 r0 bottom value=2.2uF
C106 "EMK107BB7225KA-T" 0603L 64.625,32.375 r0 bottom value=2.2uF
C107 "EMK107BB7225KA-T" 0603L 64.625,29.875 r0 bottom value=2.2uF
C108 "C0805C105K5RACTU" 0805L 83.125,33 r270 top value=1uF
C109 "Capacitor" 0402L 89,35.25 r90 bottom value=0.01uF
C110 "C0805C105K5RACTU" 0805L 80,26.75 r90 top value=1uF
C111 "Capacitor" 0402L 89,33.125 r270 bottom value=0.01uF
C112 "C0805C105K5RACTU" 0805L 83.125,33 r270 bottom value=1uF
C113 "Capacitor" 0402L 89,28.125 r90 bottom value=0.01uF
C114 "C0805C105K5RACTU" 0805L 80,26.75 r90 bottom value=1uF
C115 "Capacitor" 0402L 89,26.125 r270 bottom value=0.01uF
D1 "WARN" LED_LTST-C170 57.5,3.75 r0 top value=Yellow
D2 "FAULT" LED_LTST-C170_Red 51.25,3.75 r0 top value=Red
D3 "USB RDY" LTST-C170TBKT_Blue 18.75,43.75 r180 top value=Blue
D4 "SPDIF LOCK" LTST-C170TBKT_Blue 6.25,35 r180 top value=Blue
D5 "3.3V" LTST-C170KGKT_Green 45.75,81.75 r0 top value=Green
FID1 "DNP" Fiducial6.4-20 83.75,81.25 r90 top
FID2 "DNP" Fiducial6.4-20 10,2.5 r90 top
FID3 "DNP" Fiducial6.4-20 10,82.5 r90 top
FID4 "DNP" Fiducial6.4-20 10,82.5 r90 bottom
FID5 "DNP" Fiducial6.4-20 83.75,81.25 r90 bottom
FID6 "DNP" Fiducial6.4-20 10,2.5 r90 bottom
H1 "HeatSink_2" HEATSINK-DKQ56_20MMX41_4X32_77MM 60,37.5 r0 top locked
H6 "M3" Keystone_24434 91.5,81.5 r180 bottom
H7 "M3" Keystone_24434 3.5,3.5 r180 bottom
H8 "M3" Keystone_24434 91.5,3.5 r180 bottom
H9 "M3" Keystone_24434 3.5,81.5 r180 bottom
J1 "OUTPUT" On-Shore_ED555_8DS 91,37.5 r90 top locked
J2 "SDIN2" PBC03SAAN 42.46,20.25 r0 top
J3 "475890001" Molex_0475890001 0,70 r270 top
J4 "JTAG" SULLINS_LPPB061NGCN-RC 2,49 r270 top
J5 "MCLK" PBC03SAAN 42.5,40 r0 top
J6 "SCLK" PBC03SAAN 42.5,35 r0 top
J7 "FSYNC" PBC03SAAN 42.5,30 r0 top
J8 "SDIN1" PBC03SAAN 42.5,25 r0 top
J10 "Receptacle_4x1" TERM_BLK_ED555-4DS 90.75,61 r90 top locked
J12 "DNP" Sullins_PBC02SAAN 37.5,74.375 r0 top
J13 "VBAT" Sullins_PBC02SAAN 62.5,62.5 r90 top
J14 "I2C" PBC03SAAN 42.5,50.085 r90 top
L1 "VCMT053T-3R3MN5" VCMT053T 75,49 r0 bottom value=3.3uH
L2 "VCMT053T-3R3MN5" VCMT053T 78,41.25 r0 bottom value=3.3uH
L3 "MPZ2012S300AT000" MPZ2012 5.125,74.125 r0 bottom value="30 ohm"
L4 "VCMT053T-1R5MN5" VCMT053T 68.075,72.75 r180 top value=1.5uH
L5 "Ferrite_Bead" NFZ2M 60.625,76.25 r180 top value="180 ohm"
L6 "LQM2HPN2R2MG0L" 1008 26.375,77.75 r180 bottom value=2.2uH
L7 "VCMT053T-3R3MN5" VCMT053T 75,49 r0 top value=3.3uH
L8 "VCMT053T-3R3MN5" VCMT053T 78,41.25 r0 top value=3.3uH
L9 "VCMT053T-3R3MN5" VCMT053T 78,33.75 r0 top value=3.3uH
L10 "VCMT053T-3R3MN5" VCMT053T 75,26 r0 top value=3.3uH
L11 "VCMT053T-3R3MN5" VCMT053T 78,33.75 r0 bottom value=3.3uH
L12 "VCMT053T-3R3MN5" VCMT053T 75,26 r0 bottom value=3.3uH
Logo1 "Texas Instruments" TI_Stacked_Overlay_Small 73,10.5 r0 top
Logo2 "FCC disclaimer" FCC_disclaimer_stacked 24.5,81.25 r0 top
Logo3 "WEEE logo" WEEE_Minimum 90.125,17.75 r0 top
Logo4 "CE Mark" CE_Mark_5mm 82.5,16.75 r0 top
Q1 "MMBT3906-7-F" SOT-23 4.875,32.5 r0 bottom value="40 V"
R2 "DNP" 0402L 50,32.25 r180 top value=4.99k
R3 "" 0402L 50,33.125 r0 top value=4.99k
R4 "DNP" 0402L 50,31.375 r180 top value=4.99k
R5 "" 0402L 50,30.5 r0 top value=4.99k
R6 "Resistor" 0402L 36.25,10 r180 bottom value=1.00k
R7 "Resistor" 0402L 56.5,6.75 r90 bottom value=4.99k
R8 "" 0402L 46.25,10 r180 bottom value=1.00k
R9 "Resistor" 0402L 50.25,6.75 r90 bottom value=4.99k
R10 "ERJ-2RKF1001X" 0402L 7.375,61.75 r0 bottom value=1.00k
R11 "ERJ-2RKF2201X" 0402L 6.875,41 r270 bottom value=2.20k
R12 "ERJ-2RKF2201X" 0402L 6.875,38.25 r90 bottom value=2.20k
R13 "RC0603FR-074R75L" 0603L 26.875,48.75 r180 bottom value=4.75
R14 "Resistor" 0201L 23.25,67.5 r90 bottom value=33.2
R15 "RC0402FR-0747KL" 0402L 28.125,64 r0 bottom value=47.0k
R16 "RC0402FR-0747KL" 0402L 28.125,63.125 r0 bottom value=47.0k
R17 "RC0402FR-0747KL" 0402L 28.125,62.25 r0 bottom value=47.0k
R18 "RC0402FR-0747KL" 0402L 28.125,61.375 r0 bottom value=47.0k
R19 "RC0402FR-0710KL" 0402L 20,67.5 r90 bottom value=10.0k
R20 "RC0603FR-07680RL" 0603L 23.75,43.75 r180 top value=680
R21 "Resistor" 0201L 27.5,66.25 r0 bottom value=33.2
R22 "Resistor" 0201L 27.5,65 r0 bottom value=33.2
R23 "Resistor" 0201L 7.5,56.125 r180 bottom value=33.2
R24 "RC0402FR-0710KL" 0402L 15,67.5 r90 bottom value=10.0k
R25 "Resistor" 0201L 7.5,52.125 r180 bottom value=33.2
R26 "ERJ-2RKF1003X" 0402L 7.375,72.125 r270 top value=100k
R27 "RC0603FR-0743R2L" 0603L 17.875,67.5 r270 bottom value=43.2
R28 "Resistor" 0201L 12.75,46.125 r180 bottom value=33.2
R29 "Resistor" 0201L 26.25,36.5 r0 bottom value=33.2
R30 "Resistor" 0201L 26.25,38.25 r0 bottom value=33.2
R31 "Resistor" 0201L 21.625,45.375 r180 bottom value=25.5k
R32 "RC0201FR-0710K2L" 0201L 19.625,48.25 r270 bottom value=10.2k
R33 "RC0201FR-0710K2L" 0201L 13.125,47.125 r90 bottom value=10.2k
R34 "RC0201FR-0710K2L" 0201L 19.625,45.5 r90 bottom value=10.2k
R35 "Resistor" 0201L 21.625,46 r0 bottom value=51.0k
R36 "ERJ-2GE0R00X" 0402L 13.625,48.125 r180 bottom value=0
R37 "Resistor" 0402L 13.75,22.75 r0 top value=49.9
R38 "Resistor" 0402L 37.5,40 r180 top value=49.9
R39 "Resistor" 0402L 20.75,28.75 r90 top value=49.9
R40 "Resistor" 0402L 27.5,28.25 r0 top value=49.9
R41 "Resistor" 0402L 37.5,35 r180 top value=49.9
R42 "Resistor" 0402L 27.5,26.75 r0 top value=49.9
R43 "Resistor" 0603L 24,21.875 r180 top value=470
R44 "Resistor" 0402L 23.75,26.5 r90 top value=49.9
R45 "Resistor" 0402L 37.5,30 r180 top value=49.9
R46 "Resistor" 0402L 17.5,14.5 r270 top value=4.99k
R47 "Resistor" 0402L 15.25,17 r180 bottom value=100
R48 "Resistor" 0402L 3.75,30 r270 bottom value=4.99k
R49 "Resistor" 0402L 22.125,30 r90 bottom value=49.9
R50 "Resistor" 0402L 13.75,20.875 r0 top value=681
R51 "Resistor" 0402L 19.5,14.5 r270 top value=100k
R52 "DNP" 0402L 13.75,29.375 r90 top value=4.99k
R53 "Resistor" 0402L 15,29.375 r270 top value=4.99k
R54 "Resistor" 0402L 20.5,31.75 r0 bottom value=10.0k
R55 "Resistor" 0402L 17.5,29.375 r90 top value=4.99k
R56 "DNP" 0402L 16.25,29.375 r270 top value=4.99k
R57 "Resistor" 0402L 5.625,35 r180 bottom value=360
R58 "Resistor" 0402L 50.25,81.75 r0 top value=360
R59 "RC0603FR-0766K5L" 0603L 31.375,72.5 r0 bottom value=66.5k
R61 "RC0603FR-07100KL" 0603L 28.75,72.5 r0 bottom value=100k
S1 "STANDBY" SW_FT1D-4M-Z 35,0.5 r90 top locked
S2 "MUTE" SW_FT1D-4M-Z 45,0.5 r90 top locked
S3 "SPDIF POWER" SW_FT1D-4M-Z 25,0.5 r90 top locked
S4 "XMOS ENABLE" SW_FT1D-4M-Z 15,0.5 r90 top locked
SH1 "SNT-100-BK-G" SNT-100-BK-G 62.5,62.5 r0 top value=1x2
SH2 "SNT-100-BK-G" SNT-100-BK-G 41.25,40 r0 top value=1x2
SH3 "SNT-100-BK-G" SNT-100-BK-G 41.25,35 r0 top value=1x2
SH4 "SNT-100-BK-G" SNT-100-BK-G 41.25,30 r0 top value=1x2
SH5 "SNT-100-BK-G" SNT-100-BK-G 41.25,25.125 r0 top value=1x2
SH6 "SNT-100-BK-G" SNT-100-BK-G 41.25,20 r180 top value=1x2
U1 "TAS6424MSQDKQRQ1" DKQ0056A-MFG 60,37.477 r0 top
U2 "XEF216-512-TQ128-C20" TQFP-128 17.5,57.5 r0 bottom locked
U3 "OSC_4P_1_OE-STBY" Abracon_ASTMLPA 14.75,45.25 r90 bottom
U4 "SN74AVC2T244DQER" DQE0008A 9.5,45 r270 bottom
U5 "CDCE913PWR" PW0014A_L 11.25,40 r270 bottom locked
U6 "TPS3897ADRYR" DRY0006A 21.875,46.875 r90 bottom
U7 "SN74LVC2G07DSFR" DSF0006A 19.25,46.875 r180 bottom
U8 "OPTO IN" PLR135_T10 3.75,25 r90 top
U9 "74LVC2G157DCT" DCU0008A_N 33.75,40.75 r0 top
U10 "74LVC2G157DCT" DCU0008A_N 33.75,35.75 r0 top
U11 "74LVC2G157DCT" DCU0008A_N 33.75,30.75 r0 top
U12 "TI-DIR9001-Q1-TSSOP_PW-28" PW0028A_N 18.75,21.25 r180 top
U13 "74LVC2G157DCT" DCU0008A_N 23.75,32.5 r180 bottom
U14 "TPS22965DSG" DSG0008B 20,9.25 r180 bottom
U15 "TI-TL7X0MXX-Q1KVU3" KVU0003A_N 52.5,72 r270 top
U16 "TPS736xxDBV" DBV0005A_N 20,41.25 r180 bottom
U17 "TLV62568DBVR" DBV0005A_N 28.75,75 r0 bottom
Y1 "XTAL_4P_13_G24" ABRACON_ABM8G 27.375,20.875 r0 top
ZZ1 "These assemblies are ESD sensitive, ESD precautions shall be observed." AssemblyNote 102,85 r0 top
ZZ2 "These assemblies must be clean and free from flux and all contaminants. Use of no clean flux is not acceptable." AssemblyNote 102,83 r0 top
ZZ3 "These assemblies must comply with workmanship standards IPC-A-610 Class 2, unless otherwise specified." AssemblyNote 102,81 r0 top
ZZ4 "Heat Sink to be machined from AAVID Extrusion 61215." AssemblyNote 102,79 r0 top
ZZ5 "Apply Arctic Silver 5 Thermal Paste On Thermal Pad of U10 Before Mounting Heat Sink." AssemblyNote 102,77 r0 top

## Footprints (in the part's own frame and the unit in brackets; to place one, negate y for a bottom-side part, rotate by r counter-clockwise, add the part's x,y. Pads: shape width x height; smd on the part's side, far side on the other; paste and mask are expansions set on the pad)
0201L [mm] "Data from Kemet datasheet CC101_COM dated 7/28/11"
  rect 0.36x0.32 smd mask+0.048: 1(-0.28,0) 2(0.28,0)
  body extent -0.31,-0.16 0.31,0.16, height 0.26
0402L [mm] "0402 from SM-752 data"
  rect 0.6x0.5 smd: 1(-0.5,0) 2(0.5,0)
  body extent -0.55,-0.3 0.55,0.3, height 0.6
0603L [mm] "0603 from SM-752 data"
  rect 0.8x0.85 smd: 1(-0.7,0) 2(0.7,0)
  silkscreen extent -0.07,-0.33 0.07,0.33, body extent -0.87,-0.47 0.87,0.47, height 1
0805L [mm] "0805 from SM-752 data"
  rect 1.1x1.4 smd: 1(-0.75,0) 2(0.75,0)
  body extent -1.1,-0.72 1.1,0.72, height 1.45
1008 [mm] "SMD, Body 2.5x2mm, Height 1.2mm"
  rect 0.8x2.2 smd: 1(-1,0) 2(1,0)
  silkscreen extent -0.42,-1.25 0.43,1.38, body extent -1.35,-1.1 1.35,1.1, height 1.2
1206_190L [mm] "1206_190"
  rect 1.1x1.75 smd: 1(-1.35,0) 2(1.35,0)
  silkscreen extent -0.4,-0.77 0.4,0.77, body extent -1.75,-0.95 1.75,0.95, height 1.9
1210_280 [mm] "SMD, 2-Leads, Body 3.6x2.8mm, Height 2.8mm"
  rect 1.1x2.2 smd: 1(-1.65,0) 2(1.65,0)
  silkscreen extent -0.84,-1.4 0.84,1.4, body extent -1.8,-1.4 1.8,1.4, height 2.8
ABRACON_ABM8G [mm] "ABRACON"
  rect 1.2x1.4 smd: 1(-0.85,1.1) 2(-0.85,-1.1) 3(0.85,-1.1) 4(0.85,1.1)
  silkscreen extent -1.92,-0.1 1.3,1.21, body extent -1.3,-1.65 1.3,1.65, height 1.01
Abracon_ASTMLPA [mm] "SMD, 4-Leads, Body 2x1.6mm"
  rect 0.8x0.9 smd: 1(-0.6,0.75) 2(-0.6,-0.75) 3(0.6,-0.75) 4(0.6,0.75)
  silkscreen extent -1.46,0.74 -1.34,0.86, body extent -0.8,-1 0.8,1, height 0.75
AssemblyNote [mm] "Assembly Note"
BT_1000x2000 [mm] "TH, 2-Leads, Dia 10mm, Pin Spacing 5mm"
  rect 1.35x1.35 hole 0.85: 1(-2.5,0)
  round 1.35 hole 0.85: 2(2.5,0)
  silkscreen extent -6.86,-5.4 5.4,5.4, body extent -5.36,-5.39 5.39,5.39, height 22.01
CE_Mark_5mm [mm] "Minimum text height for CE Mark"
  silkscreen extent -3.5,-2.5 3.5,2.5
DBV0005A_N [mm] "SOT23, 5-Leads, Body 2.9x1.6mm, Pitch 0.95mm, Lead Span 2.8mm, IPC Medium Density"
  rrect17% 1x0.6 smd: 1(-1.375,0.95) 2(-1.375,0) 3(-1.375,-0.95) 4(1.375,-0.95) 5(1.375,0.95)
  silkscreen extent -1.63,-1.55 0.38,1.55, body extent -1.42,-1.46 1.42,1.46, height 1.09
DCU0008A_N [mm] "TSSOP, 8-Leads, Body 2x2.3mm, Pitch 0.5mm, IPC Medium Density"
  oval 0.8x0.3 smd: 1(-1.6,0.75) 2(-1.6,0.25) 3(-1.6,-0.25) 4(-1.6,-0.75) 5(1.6,-0.75) 6(1.6,-0.25) 7(1.6,0.25) 8(1.6,0.75)
  silkscreen extent -1.05,-1.05 0.38,1.05, body extent -1.56,-1 1.56,1, height 0.9
DKQ0056A-MFG [mm]
  rrect25% 1.9x0.4 smd paste+0 mask+0: 1(-4.75,8.572) 2(-4.75,7.938) 3(-4.75,7.302) 4(-4.75,6.667) 5(-4.75,6.032) 6(-4.75,5.397) 7(-4.75,4.763) 8(-4.75,4.127) 9(-4.75,3.492) 10(-4.75,2.857) 11(-4.75,2.222) 12(-4.75,1.587) 13(-4.75,0.953) 14(-4.75,0.318) 15(-4.75,-0.318) 16(-4.75,-0.953) 17(-4.75,-1.587) 18(-4.75,-2.222) 19(-4.75,-2.857) 20(-4.75,-3.492) 21(-4.75,-4.127) 22(-4.75,-4.763) 23(-4.75,-5.397) 24(-4.75,-6.032) 25(-4.75,-6.667) 26(-4.75,-7.302) 27(-4.75,-7.938) 28(-4.75,-8.572) 29(4.75,-8.572) 30(4.75,-7.938) 31(4.75,-7.302) 32(4.75,-6.667) 33(4.75,-6.032) 34(4.75,-5.397) 35(4.75,-4.763) 36(4.75,-4.127) 37(4.75,-3.492) 38(4.75,-2.857) 39(4.75,-2.222) 40(4.75,-1.587) 41(4.75,-0.953) 42(4.75,-0.318) 43(4.75,0.318) 44(4.75,0.953) 45(4.75,1.587) 46(4.75,2.222) 47(4.75,2.857) 48(4.75,3.492) 49(4.75,4.127) 50(4.75,4.763) 51(4.75,5.397) 52(4.75,6.032) 53(4.75,6.667) 54(4.75,7.302) 55(4.75,7.938) 56(4.75,8.572)
  silkscreen extent -6.39,-9.27 3.42,9.27, body extent -5.8,-9.52 5.8,9.52, height 0.25
DQE0008A [mm] "SON, 8-Leads, Body 1.4x1mm, Pitch 0.35mm, TI Recommended"
  rect 0.6x0.16 smd: 1(-0.4,0.525)
  rect 0.5x0.16 smd: 2(-0.45,0.175) 3(-0.45,-0.175) 4(-0.45,-0.525) 5(0.45,-0.525) 6(0.45,-0.175) 7(0.45,0.175) 8(0.45,0.525)
  silkscreen extent -0.7,-0.85 0.4,0.85, body extent -0.53,-0.72 0.53,0.73, height 0.41
DRY0006A [mm] "USON-6"
  rrect67% 0.45x0.3 smd paste-0.05 mask-0.05: 1(-0.275,0.5)
  rrect67% 0.4x0.3 smd paste-0.05 mask-0.05: 2(-0.3,0) 3(-0.3,-0.5) 4(0.3,-0.5) 5(0.3,0) 6(0.3,0.5)
  body extent -0.5,-0.72 0.5,0.72, height 0.58
DSF0006A [mm] "TI recommended land pattern"
  rrect59% 0.6x0.17 smd mask+0.045: 1(-0.4,0.35) 2(-0.4,0) 3(-0.4,-0.35) 4(0.4,-0.35) 5(0.4,0) 6(0.4,0.35)
  silkscreen extent -0.6,-0.63 0.6,0.63, body extent -0.5,-0.5 0.5,0.5, height 0.48
DSG0008B [mm] "SON, 8-Leads, Body 2x2mm, Pitch 0.5mm, Thermal Pad 1.6x0.9mm, TI Recommended"
  rrect14% 0.9x0.7 on Bottom Paste: 0(0,-0.45) 0(0,0.45)
  rrect40% 0.5x0.25 smd: 1(-0.95,0.75) 2(-0.95,0.25) 3(-0.95,-0.25) 4(-0.95,-0.75) 5(0.95,-0.75) 6(0.95,-0.25) 7(0.95,0.25) 8(0.95,0.75)
  rrect11% 0.9x1.6 smd paste-0.45: 9(0,0)
  silkscreen extent -1.07,-1.15 1.07,1.15, body extent -1,-1 1,1, height 0.77
FC_500x1100 [mm] "TH, 2-Leads, Dia 5mm,  Lead Spacing 2mm"
  rect 1.35x1.35 hole 0.85: 1(-1,0)
  round 1.35 hole 0.85: 2(1,0)
  silkscreen extent -2.75,-2.75 2.75,2.75, body extent -2.73,-2.75 2.75,2.75, height 12.51
FCC_disclaimer_stacked [mm]
Fiducial6.4-20 [mm]
  round 0.635 smd mask+0.683: 1(0,0)
  Top Layer keep-out circle w1.178: c0,0 r0.5
HEATSINK-DKQ56_20MMX41_4X32_77MM [mm] "Heat Sink for DKQ Packages, 41.4x20 mm"
  round 6 hole 3: 1(0,16.25) 2(0,-16.25)
  silkscreen extent -10,-20.7 10,20.7, body extent -10,-20.7 10,20.7, height 32.77
Keystone_24434 [mm] "Keystone"
  body extent -2.89,-2.5 2.89,2.5, height 12
KVU0003A_N [mm] "DPAK, 3-Leads, Body 6.6x6.1mm, Pitch 2.29mm, IPC Medium Density"
  rrect10% 2.8x1 smd: 1(-3.87,2.29) 3(-3.87,-2.29)
  rrect10% 0.98x1.13 on Top Paste: 4(0.47,1.995) 4(0.47,0.665) 4(0.47,-0.665) 4(0.47,-1.995) 4(1.65,1.995) 4(1.65,-0.665) 4(1.65,0.665) 4(1.65,-1.995) 5(2.83,1.995) 5(2.83,-0.665) 5(2.83,0.665) 5(2.83,-1.995) 6(4.01,1.995) 6(4.01,-0.665) 6(4.01,0.665) 6(4.01,-1.995) 7(5.19,1.995) 7(5.19,-0.665) 7(5.19,0.665) 7(5.19,-1.995)
  rrect2% 6.3x5.55 smd paste-3: 4(2.83,0)
  silkscreen extent -4.02,-3.35 -0.72,3.47, body extent -4.72,-3.26 5.38,3.26, height 2.41
LED_LTST-C170 [mm] "LITE-ON"
  rect 1.2x1.2 smd: 1(-1.05,0) 2(1.05,0)
  silkscreen extent -1.6,-1 2.2,1, body extent -1.05,-0.67 1.05,0.67, height 1.1
LED_LTST-C170_Red [mm] "LITE-ON"
  rect 1.2x1.2 smd: 1(-1.05,0) 2(1.05,0)
  silkscreen extent -1.6,-1 2.2,1, body extent -1.05,-0.67 1.05,0.67, height 1.1
LTST-C170KGKT_Green [mm] "LITE-ON"
  rect 1.2x1.2 smd: 1(-1.05,0) 2(1.05,0)
  silkscreen extent -1.6,-1 2.2,1, body extent -1.05,-0.67 1.05,0.67, height 1.1
LTST-C170TBKT_Blue [mm] "LITE-ON"
  rect 1.2x1.2 smd: 1(-1.05,0) 2(1.05,0)
  silkscreen extent -1.6,-1 2.2,1, body extent -1.05,-0.67 1.05,0.67, height 1.2
Molex_0475890001 [mm] "Molex"
  rrect25% 0.4x1.35 smd: 1(-1.3,4.125) 2(-0.65,4.125) 3(0,4.125) 4(0.65,4.125) 5(1.3,4.125)
  oval 1.05x1.3 hole 0.7 slot 0.85 at 90 deg: 6(2.225,4.45) 11(-2.225,4.45)
  oval 0.8x2 hole 0.6 slot 1.3 at 90 deg: 7(4.175,1.45) 10(-4.175,1.45)
  rrect6% 1.8x2 smd: 8(1.15,1.45) 9(-1.15,1.45)
  Top Layer region: -4.175,0.45 -4.175,2.45 -2.6,2.45 -2.6,0.45
  Top Layer region: 2.6,0.45 2.6,2.45 4.175,2.45 4.175,0.45
  silkscreen extent -3.75,2.85 3.75,4.3, body extent -4.32,-1.3 4.33,4.59, height 2.81
MPZ2012 [mm] "TDK"
  rect 0.8x1.2 smd: 1(-0.9,0) 2(0.9,0)
  body extent -1.1,-0.72 1.1,0.72, height 1.05
NFZ2M [mm] "SMD, 2-Leads, Body 2x1.6mm"
  rect 0.9x2 smd: 1(-0.85,0) 2(0.85,0)
  body extent -1.1,-0.9 1.1,0.9, height 1
On-Shore_ED555_8DS [mm] "Terminal Block, 3.5mm, 8-Pos, TH"
  rect 2.54x2.54 hole 1.27: 1(-12.25,0)
  round 2.54 hole 1.27: 2(-8.75,0) 3(-5.25,0) 4(-1.75,0) 5(1.75,0) 6(5.25,0) 7(8.75,0) 8(12.25,0)
  silkscreen extent -14,-3.8 14,3.1, body extent -14,-3.8 14,2.7, height 8.2
PBC03SAAN [mm] "Sullins 100mil, 1x3, 230 mil above insulator"
  rect 1.65x1.65 hole 1.016: 1(-2.54,0)
  round 1.65 hole 1.016: 2(0,0) 3(2.54,0)
  silkscreen extent -3.81,-1.27 3.81,1.27, body extent -3.81,-1.27 3.81,1.27, height 8.38
PLR135_T10 [mm] "EVERLIGHT"
  rect 1.45x1.45 hole 0.813: 1(2.54,-4.67)
  round 1.45 hole 0.813: 2(0,-4.67) 3(-2.54,-4.67)
  round 1.75 hole 1.092: 4(2.54,-2.13) 5(-2.54,-2.04)
  silkscreen extent -5.05,-6.93 5.05,6.95, body extent -5,-6.9 5,6.9, height 10.3
PW0014A_L [mm] "TSOP, 14-Leads, Body 5x4.4mm, Pitch 0.65mm, IPC High Density"
  oval 1.2x0.4 smd: 1(-2.85,1.95) 2(-2.85,1.3) 3(-2.85,0.65) 4(-2.85,0) 5(-2.85,-0.65) 6(-2.85,-1.3) 7(-2.85,-1.95) 8(2.85,-1.95) 9(2.85,-1.3) 10(2.85,-0.65) 11(2.85,0) 12(2.85,0.65) 13(2.85,1.3) 14(2.85,1.95)
  silkscreen extent -3.2,-2.55 1.85,2.55, body extent -3.21,-2.5 3.21,2.5, height 1
PW0028A_N [mm] "TSOP, 28-Leads, Body 9.7x4.4mm, Pitch 0.65mm, IPC Medium Density"
  oval 1.4x0.45 smd: 1(-2.95,4.225) 2(-2.95,3.575) 3(-2.95,2.925) 4(-2.95,2.275) 5(-2.95,1.625) 6(-2.95,0.975) 7(-2.95,0.325) 8(-2.95,-0.325) 9(-2.95,-0.975) 10(-2.95,-1.625) 11(-2.95,-2.275) 12(-2.95,-2.925) 13(-2.95,-3.575) 14(-2.95,-4.225) 15(2.95,-4.225) 16(2.95,-3.575) 17(2.95,-2.925) 18(2.95,-2.275) 19(2.95,-1.625) 20(2.95,-0.975) 21(2.95,-0.325) 22(2.95,0.325) 23(2.95,0.975) 24(2.95,1.625) 25(2.95,2.275) 26(2.95,2.925) 27(2.95,3.575) 28(2.95,4.225)
  silkscreen extent -3.5,-4.9 1.5,4.9, body extent -3.21,-4.85 3.21,4.85, height 1
SNT-100-BK-G [mil] "Samtec STEP model"
  round 1 on Mech3: 0(0,0)
  body extent -100,-50 100,50, height 344
SOT-23 [mm] "SOT23, 3-Leads, Body 2.9x1.3mm, Pitch 0.95mm, Lead Span 2.5mm, IPC Medium Density"
  rrect50% 1x0.6 smd: 1(-1.2,0.95) 2(-1.2,-0.95) 3(1.2,0)
  silkscreen extent -1.62,-1.5 0.7,1.5, body extent -1.16,-1.45 1.21,1.45, height 1
SULLINS_LPPB061NGCN-RC [mm] "SULLINS"
  rect 1.05x1.05 hole 0.61: 1(3.175,2.54)
  round 1.05 hole 0.61: 2(1.905,2.54) 3(0.635,2.54) 4(-0.635,2.54) 5(-1.905,2.54) 6(-3.175,2.54)
  silkscreen extent -4,-2.37 4.03,2, body extent -4,-2.36 4,2.59, height 2.16
Sullins_PBC02SAAN [mm] "Sullins 100mil, 1x2, 230 mil above insulator"
  rect 1.65x1.65 hole 1.016: 1(0,1.27)
  round 1.65 hole 1.016: 2(0,-1.27)
  silkscreen extent -1.37,-2.54 1.27,3.1, body extent -1.27,-2.54 1.27,2.54, height 8.38
SW_FT1D-4M-Z [mm] "TH, 3-Leads, Body 5.6x5.4mm, Pitch 2.54mm"
  rect 1.5x1.5 hole 1: 1(6.025,1.27)
  round 1.5 hole 1: 2(8.565,1.27) 3(11.105,1.27) 4(0.945,1.27) 5(0.945,-1.27)
  silkscreen extent 0.8,-2.8 5.4,2.8, body extent -5.39,-2.8 11.36,2.8, height 7.01
TERM_BLK_ED555-4DS [mm]
  rect 2.54x2.54 hole 1.27: 1(0,0)
  round 2.54 hole 1.27: 2(3.5,0) 3(7,0) 4(10.5,0)
  silkscreen extent -2.36,-4.09 12.25,2.67, body extent -1.75,-3.8 12.25,2.7, height 8.2
TI_Stacked_Overlay_Small [mm]
  silkscreen extent -10.63,-2.49 10.63,2.49
TQFP-128 [mm] "TQFP, 128-Leads, Body 14x14mm, Pitch 0.4mm"
  rrect50% 1.45x0.2 smd: 1(-7.7,6.2) 2(-7.7,5.8) 3(-7.7,5.4) 4(-7.7,5) 5(-7.7,4.6) 6(-7.7,4.2) 7(-7.7,3.8) 8(-7.7,3.4) 9(-7.7,3) 10(-7.7,2.6) 11(-7.7,2.2) 12(-7.7,1.8) 13(-7.7,1.4) 14(-7.7,1) 15(-7.7,0.6) 16(-7.7,0.2) 17(-7.7,-0.2) 18(-7.7,-0.6) 19(-7.7,-1) 20(-7.7,-1.4) 21(-7.7,-1.8) 22(-7.7,-2.2) 23(-7.7,-2.6) 24(-7.7,-3) 25(-7.7,-3.4) 26(-7.7,-3.8) 27(-7.7,-4.2) 28(-7.7,-4.6) 29(-7.7,-5) 30(-7.7,-5.4) 31(-7.7,-5.8) 32(-7.7,-6.2) 65(7.7,-6.2) 66(7.7,-5.8) 67(7.7,-5.4) 68(7.7,-5) 69(7.7,-4.6) 70(7.7,-4.2) 71(7.7,-3.8) 72(7.7,-3.4) 73(7.7,-3) 74(7.7,-2.6) 75(7.7,-2.2) 76(7.7,-1.8) 77(7.7,-1.4) 78(7.7,-1) 79(7.7,-0.6) 80(7.7,-0.2) 81(7.7,0.2) 82(7.7,0.6) 83(7.7,1) 84(7.7,1.4) 85(7.7,1.8) 86(7.7,2.2) 87(7.7,2.6) 88(7.7,3) 89(7.7,3.4) 90(7.7,3.8) 91(7.7,4.2) 92(7.7,4.6) 93(7.7,5) 94(7.7,5.4) 95(7.7,5.8) 96(7.7,6.2)
  rrect50% 0.2x1.45 smd: 33(-6.2,-7.7) 34(-5.8,-7.7) 35(-5.4,-7.7) 36(-5,-7.7) 37(-4.6,-7.7) 38(-4.2,-7.7) 39(-3.8,-7.7) 40(-3.4,-7.7) 41(-3,-7.7) 42(-2.6,-7.7) 43(-2.2,-7.7) 44(-1.8,-7.7) 45(-1.4,-7.7) 46(-1,-7.7) 47(-0.6,-7.7) 48(-0.2,-7.7) 49(0.2,-7.7) 50(0.6,-7.7) 51(1,-7.7) 52(1.4,-7.7) 53(1.8,-7.7) 54(2.2,-7.7) 55(2.6,-7.7) 56(3,-7.7) 57(3.4,-7.7) 58(3.8,-7.7) 59(4.2,-7.7) 60(4.6,-7.7) 61(5,-7.7) 62(5.4,-7.7) 63(5.8,-7.7) 64(6.2,-7.7) 97(6.2,7.7) 98(5.8,7.7) 99(5.4,7.7) 100(5,7.7) 101(4.6,7.7) 102(4.2,7.7) 103(3.8,7.7) 104(3.4,7.7) 105(3,7.7) 106(2.6,7.7) 107(2.2,7.7) 108(1.8,7.7) 109(1.4,7.7) 110(1,7.7) 111(0.6,7.7) 112(0.2,7.7) 113(-0.2,7.7) 114(-0.6,7.7) 115(-1,7.7) 116(-1.4,7.7) 117(-1.8,7.7) 118(-2.2,7.7) 119(-2.6,7.7) 120(-3,7.7) 121(-3.4,7.7) 122(-3.8,7.7) 123(-4.2,7.7) 124(-4.6,7.7) 125(-5,7.7) 126(-5.4,7.7) 127(-5.8,7.7) 128(-6.2,7.7)
  rrect2% 4.8x4.8 smd paste-4.8: 129(0,0)
  silkscreen extent -7.1,-7.1 7.1,7.1, body extent -7,-7 7,7, height 1.2
VCMT053T [mm] "CYNTEC"
  rrect5% 1.9x3.3 smd: 1(-2.05,0) 2(2.05,0)
  silkscreen extent -2.8,-2.85 2.8,2.85, body extent -2.9,-2.72 2.9,2.72, height 3.02
WEEE_Minimum [mm] "WEEElie bin"
  silkscreen extent -2.42,-4.38 2.52,2.65

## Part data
C1 C10 C12 C96: library part CMP-0006867-4, "CAP, CERM, 1 uF, 25 V, +/- 10%, X7R, 0603", Cap_Case=0603, Manufacturer=Kemet, Supplier Part Number 1=399-7376-1-ND, TempCo=X7R, Tolerance_%=10%, Value1=Unknown, Value2=25V, ValueDisplayed=1uF
C2 C4 C82 C94: library part CMP-0007508-5, "CAP, CERM, 1 uF, 50 V, +/- 10%, X7R, 0603", Cap_Case=0603, Manufacturer="Taiyo Yuden", PartNumber=UMK107AB7105KA-T, Supplier Part Number 1=587-3247-1-ND, TempCo=X7R, Tolerance_%=10%, Value1=Unknown, Value2=50V, ValueDisplayed=1uF
C3 C5 C11 C93 C95: library part CMP-0006861-4, "CAP, CERM, 0.1 uF, 50 V, +/- 10%, X7R, 0603", Cap_Case=0603, Manufacturer=Kemet, Supplier Part Number 1=399-5089-1-ND, TempCo=X7R, Tolerance_%=10%, Value1=Unknown, Value2=50V, ValueDisplayed=0.1uF
C6 C9 C15 C16 C97 C98 C104 C105 C106 C107: library part CMP-0007121-4, "CAP, CERM, 2.2 uF, 16 V, +/- 10%, X7R, 0603", Cap_Case=0603, Manufacturer="Taiyo Yuden", Supplier Part Number 1=EMK107BB7225KA-T-ND, TempCo=X7R, Tolerance_%=10%, Value1=Unknown, Value2=16V, ValueDisplayed=2.2uF
C7 C13 C99 C101 C108 C110 C112 C114: library part CMP-0007730-2, "CAP, CERM, 1 uF, 50 V, +/- 10%, X7R, 0805", Cap_Case=0805, Manufacturer=Kemet, Supplier Part Number 1=399-7409-1-ND, TempCo=X7R, Tolerance_%=10%, Value1=Unknown, Value2=50V, ValueDisplayed=1uF
C8 C14 C100 C102 C109 C111 C113 C115: library part CMP-0006355-2, "CAP, CERM, 0.01 uF, 50 V, +/- 10%, C0G/NP0, 0402", Cap_Case=0402, Manufacturer=MuRata, PartNumber=GCM155R71H103KA55D, Supplier Part Number 1=490-4762-1-ND, TempCo=C0G/NP0, Tolerance_%=10%, Value1=Unknown, Value2=50V, ValueDisplayed=0.01uF
C17 C18 C56 C66 C67 C70 C73 C74 C75 C76 C85: library part CMP-0006237-2, "CAP, CERM, 0.1 uF, 16 V, +/- 10%, X7R, AEC-Q200 Grade 1, 0402", Cap_Case=0402, Manufacturer=Kemet, Supplier Part Number 1=399-6828-1-ND, TempCo=X7R, Tolerance_%=10%, Value1=Unknown, Value2=16V, ValueDisplayed=0.1uF
C19 C20 C21 C22 C23 C29 C30 C31 C32 C33 C40 C41 C42 C43: library part CMP-0006297-2, "CAP, CERM, 0.1 uF, 50 V, +/- 10%, X7R, 0402", Cap_Case=0402, Manufacturer=TDK, PartNumber=C1005X7R1H104K050BB, Supplier Part Number 1=445-5932-1-ND, TempCo=X7R, Tolerance_%=10%, Value1="0.039064 ohm", Value2=50V, ValueDisplayed=0.1uF
C24 C25 C26 C27 C28 C34 C35 C36 C37 C38 C39 C44 C45 C47 C49 C50 C51 C52 C53 C54 C55 C91: library part CMP-0006297-2, "CAP, CERM, 0.1 uF, 50 V, +/- 10%, X7R, 0402", Cap_Case=0402, Manufacturer=TDK, Supplier Part Number 1=445-5932-1-ND, TempCo=X7R, Tolerance_%=10%, Value1="0.039064 ohm", Value2=50V, ValueDisplayed=0.1uF
C46: library part CMP-0064934-4, "CAP, CERM, 2.2 uF, 16 V,+/- 10%, X7R, 0603", Cap_Case=0603, Manufacturer="Taiyo Yuden", Supplier Part Number 1=587-4864-1-ND, TempCo=X7R, Tolerance_%=10%, Value1=Unknown, Value2=16V, ValueDisplayed=2.2uF
C48: library part CMP-0860800-1, "CAP, CERM, 470 pF, 50 V,+/- 5%, C0G, AEC-Q200 Grade 1, 0402", Cap_Case=0402, Manufacturer=MuRata, TempCo=C0G, Tolerance_%=5%, Value2=50V, ValueDisplayed=470pF
C57 C60 C61 C62 C63: library part CMP-0006215-2, "CAP, CERM, 10 pF, 50 V, +/- 5%, C0G/NP0, 0402", Cap_Case=0402, Manufacturer="Wurth Elektronik", Supplier Part Number 1=732-7469-1-ND, TempCo=C0G/NP0, Tolerance_%=5%, Value1=Unknown, Value2=50V, ValueDisplayed=10pF
C58 C59: library part CMP-0006887-4, "CAP, CERM, 18 pF, 50 V, +/- 5%, C0G/NP0, 0603", Cap_Case=0603, Manufacturer=Kemet, Supplier Part Number 1=399-1052-1-ND, TempCo=C0G/NP0, Tolerance_%=5%, Value1=Unknown, Value2=50V, ValueDisplayed=18pF
C64 C65: library part CMP-0007003-5, "CAP, CERM, 10 uF, 10 V, +/- 20%, X5R, 0603", Cap_Case=0603, Manufacturer=TDK, PartNumber=C1608X5R1A106M080AC, Supplier Part Number 1=445-6853-1-ND, TempCo=X5R, Tolerance_%=20%, Value1="0.0078 ohm", Value2=10V, ValueDisplayed=10uF
C68: library part CMP-0860557-1, "CAP, CERM, 4700 pF, 25 V,+/- 10%, X7R, 0402", Cap_Case=0402, Manufacturer=Yageo, TempCo=X7R, Tolerance_%=10%, Value2=25V, ValueDisplayed=4700pF
C69: library part CMP-0006331-2, "CAP, CERM, 0.068 uF, 50 V, +/- 10%, X7R, AEC-Q200 Grade 1, 0402", Cap_Case=0402, Manufacturer=TDK, Supplier Part Number 1=445-6898-1-ND, TempCo=X7R, Tolerance_%=10%, Value1="0.05606 ohm", Value2=50V, ValueDisplayed=0.068uF
C71 C77 C88: library part CMP-0006372-2, "CAP, CERM, 1 uF, 6.3 V, +/- 20%, X5R, 0402", Cap_Case=0402, Manufacturer=MuRata, Supplier Part Number 1=490-10006-1-ND, TempCo=X5R, Tolerance_%=20%, Value1=Unknown, Value2=6.3V, ValueDisplayed=1uF
C72: library part CMP-0006308-2, "CAP, CERM, 100 pF, 50 V, +/- 5%, C0G/NP0, AEC-Q200 Grade 1, 0402", Cap_Case=0402, Manufacturer=TDK, Supplier Part Number 1=445-5596-1-ND, TempCo=C0G/NP0, Tolerance_%=5%, Value1=Unknown, Value2=50V, ValueDisplayed=100pF
C78: library part CMP-0079604-1, "CAP, CERM, 4.7 µF, 50 V,+/- 10%, X7R, AEC-Q200 Grade 1, 1210", Cap_Case=1210, Manufacturer=Kemet, Supplier Part Number 1=399-7049-1-ND, TempCo=X7R, Tolerance_%=10%, Value2=50V, ValueDisplayed=4.7µF
C79: library part CMP-0007669-2, "CAP, CERM, 0.082 uF, 50 V, +/- 10%, X7R, 0805", Cap_Case=0805, Manufacturer=AVX, PartNumber=08055C823KAT2A, Supplier Part Number 1=478-1394-1-ND, TempCo=X7R, Tolerance_%=10%, Value1="0.026 ohm", Value2=50V, ValueDisplayed=0.082uF
C80: library part CMP-0007601-2, "CAP, CERM, 2200 pF, 50 V, +/- 5%, C0G/NP0, 0805", Cap_Case=0805, Manufacturer=AVX, Supplier Part Number 1=478-1330-1-ND, TempCo=C0G/NP0, Tolerance_%=5%, Value1="0.08 ohm", Value2=50V, ValueDisplayed=2200pF
C81: library part CMP-0010530-2, "CAP, AL, 330 uF, 35 V, +/- 20%, AEC-Q200 Grade 1, TH", Cap_Case=10x20mm, Manufacturer=Nichicon, PartNumber=UBT1V331MPD1TD, Supplier Part Number 1=493-13112-1-ND, Tolerance_%=20%, Value1=Unknown, Value2=35V, ValueDisplayed=330uF
C83: library part CMP-0086153-1, "CAP, CERM, 10 µF, 50 V,+/- 10%, X5R, 1206", Cap_Case=1206, Manufacturer="Taiyo Yuden", TempCo=X5R, Tolerance_%=10%, Value2=50V, ValueDisplayed=10µF
C84: library part CMP-0006858-4, "CAP, CERM, 0.1 uF, 50 V, +/- 5%, X7R, 0603", Cap_Case=0603, Manufacturer=Kemet, Supplier Part Number 1=399-7844-1-ND, TempCo=X7R, Tolerance_%=5%, Value1=Unknown, Value2=50V, ValueDisplayed=0.1uF
C86: library part CMP-0010336-1, "CAP, AL, 47 uF, 16 V, +/- 20%, 0.8 ohm, AEC-Q200 Grade 2, TH", Cap_Case=5x11mm, Manufacturer=Panasonic, PartNumber=EEU-FC1C470, Supplier Part Number 1=P11196-ND, Tolerance_%=20%, Value1="0.8 ohm", Value2=16V, ValueDisplayed=47uF
C87: library part CMP-0082012-1, "CAP, CERM, 1 µF, 16 V,+/- 20%, X7R, 0603", Cap_Case=0603, Manufacturer=Samsung, Supplier Part Number 1=1276-6524-1-ND, TempCo=X7R, Tolerance_%=20%, Value2=16V, ValueDisplayed=1µF
C89 C90 C103: library part CMP-0007005-5, "CAP, CERM, 22 uF, 10 V, +/- 20%, X5R, 0603", Cap_Case=0603, Manufacturer=TDK, Supplier Part Number 1=445-9077-1-ND, TempCo=X5R, Tolerance_%=20%, Value1="0.00371 ohm", Value2=10V, ValueDisplayed=22uF
C92: library part CMP-0860544-1, "CAP, CERM, 0.01 µF, 6.3 V,+/- 10%, X7R, 0402", Cap_Case=0402, Manufacturer=Walsin, TempCo=X7R, Tolerance_%=10%, Value2=6.3V, ValueDisplayed=0.01µF
D1: library part CMP-0002862-2, "LED, Yellow , SMD", Color=yellow, Manufacturer=Lite-On, PartNumber=LTST-C170KSKT, Value1=W, Value2=2V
